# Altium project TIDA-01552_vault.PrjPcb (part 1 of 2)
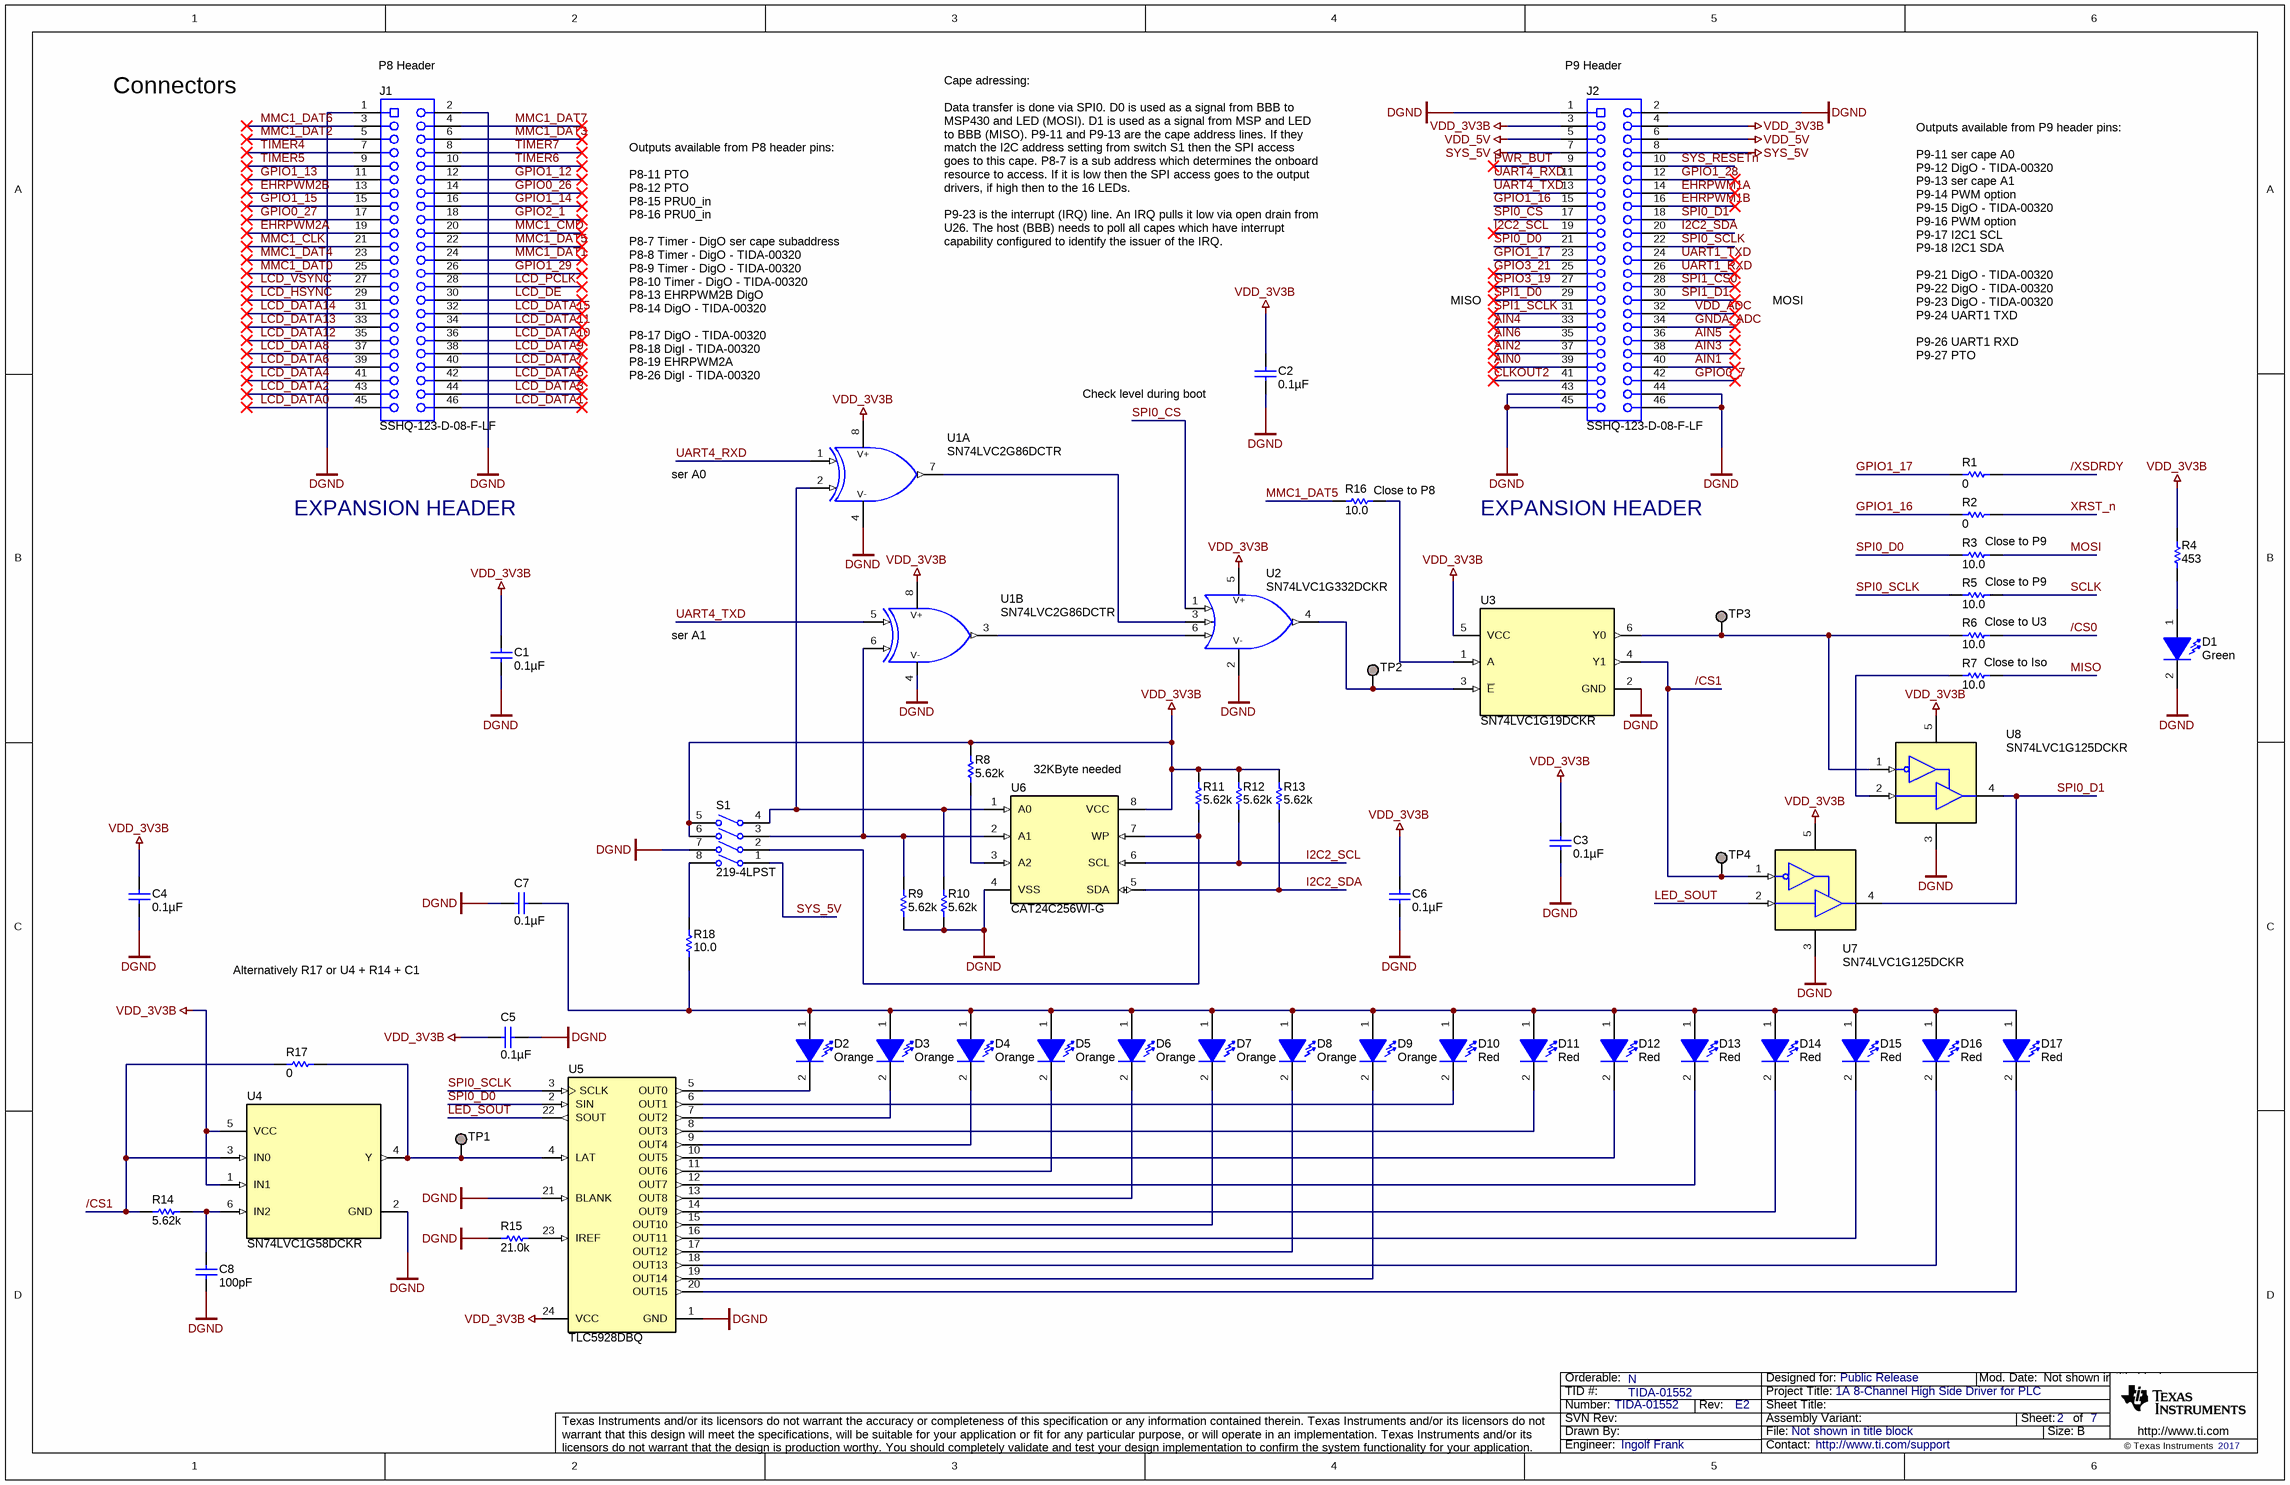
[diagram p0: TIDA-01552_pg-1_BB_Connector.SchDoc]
CopyrightYear: 2017; EVM_Orderable: N; PCB_Layout: Ingolf Frank; PCB_Rev: E2; PRJ_Customer: Public Release; PRJ_Engineer: Ingolf Frank; PRJ_Number: TIDA-01552; PRJ_Title: 1A 8-Channel High Side Driver for PLC; SCH_Rev: E2; TechSupport: http://www.ti.com/support; TID: TIDA-01552
6 sheets, 253 parts. Net scope: global (net labels, ports and power ports of the same name join across sheets).
Board file: TIDA-01552_TID.PcbDoc
Sheets:
  TIDA-01552_pg-1_BB_Connector.SchDoc
  TIDA-01552_pg-2_PSU-ISO.SchDoc
  TIDA-01552_pg-3_MCU.SchDoc
  TIDA-01552_pg-4_Driver.SchDoc
  TIDA-01552_pg-5_OP_Connector.SchDoc
  TIDA-01552_TID_Hardware.SchDoc

## Sheet TIDA-01552_pg-1_BB_Connector.SchDoc
size 431 x 279 mm; Date: Not shown in title block; ApprovedBy: Not shown in title block; CheckedBy: Not shown in title block; Author: Not shown in title block; CompanyName: Not shown in title block; Engineer: Not shown in title block; Organization: Not shown in title block; Address1: Not shown in title block; Address2: Not shown in title block; Address3: Not shown in title block; Address4: Not shown in title block; DocumentNumber: 2; Revision: Use project parameter SCH_Rev; SheetNumber: 2; SheetTotal: 7; PageSetup: Record=PageOptions¦CenterHorizontal=True¦CenterVertical=True¦PrintScale=1.00¦XCorrection=1.00¦YCorrection=1.00¦PrintKind=0¦BorderSize=5000000¦LeftOffset=0¦BottomOffset=0¦Orientation=2¦PaperLength=1000¦PaperWidth=1000¦Scale=100¦PaperSource=15¦PrintQuality=600¦MediaType=1¦DitherType=10¦PaperKind=Letter¦PrintScaleMode=1

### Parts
C1  ValueDisplayed: 0.1µF  [0603]  (hidden comment: GRM188R71C104KA01D)
C2  ValueDisplayed: 0.1µF  [0603]  (hidden comment: GRM188R71C104KA01D)
C3  ValueDisplayed: 0.1µF  [0603]  (hidden comment: GRM188R71C104KA01D)
C4  ValueDisplayed: 0.1µF  [0603]  (hidden comment: GRM188R71C104KA01D)
C5  ValueDisplayed: 0.1µF  [0603]  (hidden comment: GRM188R71C104KA01D)
C6  ValueDisplayed: 0.1µF  [0603]  (hidden comment: GRM188R71C104KA01D)
C7  ValueDisplayed: 0.1µF  [0603]  (hidden comment: GRM188R71C104KA01D)
C8  ValueDisplayed: 100pF  [0603]  (hidden comment: GRM1885C1H101JA01D)
D1  value Green  [LED_LTST-C190_G]  (hidden comment: LTST-C190KGKT)
D2  value Orange  [LED_LTST-C190]  (hidden comment: LTST-C190KFKT)
D3  value Orange  [LED_LTST-C190]  (hidden comment: LTST-C190KFKT)
D4  value Orange  [LED_LTST-C190]  (hidden comment: LTST-C190KFKT)
D5  value Orange  [LED_LTST-C190]  (hidden comment: LTST-C190KFKT)
D6  value Orange  [LED_LTST-C190]  (hidden comment: LTST-C190KFKT)
D7  value Orange  [LED_LTST-C190]  (hidden comment: LTST-C190KFKT)
D8  value Orange  [LED_LTST-C190]  (hidden comment: LTST-C190KFKT)
D9  value Orange  [LED_LTST-C190]  (hidden comment: LTST-C190KFKT)
D10  value Red  [LED_LTST-C190_Red]  (hidden comment: LTST-C190CKT)
D11  value Red  [LED_LTST-C190_Red]  (hidden comment: LTST-C190CKT)
D12  value Red  [LED_LTST-C190_Red]  (hidden comment: LTST-C190CKT)
D13  value Red  [LED_LTST-C190_Red]  (hidden comment: LTST-C190CKT)
D14  value Red  [LED_LTST-C190_Red]  (hidden comment: LTST-C190CKT)
D15  value Red  [LED_LTST-C190_Red]  (hidden comment: LTST-C190CKT)
D16  value Red  [LED_LTST-C190_Red]  (hidden comment: LTST-C190CKT)
D17  value Red  [LED_LTST-C190_Red]  (hidden comment: LTST-C190CKT)
J1  SSHQ-123-D-08-F-LF  [Major_BBB_SSHQ-123-D-08]
J2  SSHQ-123-D-08-F-LF  [Major_BBB_SSHQ-123-D-08]
R1  ValueDisplayed: 0  [0603]  (hidden comment: CRCW06030000Z0EA)
R2  ValueDisplayed: 0  [0603]  (hidden comment: CRCW06030000Z0EA)
R3  ValueDisplayed: 10.0  [0603]  (hidden comment: CRCW060310R0FKEA)
R4  ValueDisplayed: 453  [0603]  (hidden comment: CRCW0603453RFKEA)
R5  ValueDisplayed: 10.0  [0603]  (hidden comment: CRCW060310R0FKEA)
R6  ValueDisplayed: 10.0  [0603]  (hidden comment: CRCW060310R0FKEA)
R7  ValueDisplayed: 10.0  [0603]  (hidden comment: CRCW060310R0FKEA)
R8  ValueDisplayed: 5.62k  [0603]  (hidden comment: CRCW06035K62FKEA)
R9  ValueDisplayed: 5.62k  [0603]  (hidden comment: CRCW06035K62FKEA)
R10  ValueDisplayed: 5.62k  [0603]  (hidden comment: CRCW06035K62FKEA)
R11  ValueDisplayed: 5.62k  [0603]  (hidden comment: CRCW06035K62FKEA)
R12  ValueDisplayed: 5.62k  [0603]  (hidden comment: CRCW06035K62FKEA)
R13  ValueDisplayed: 5.62k  [0603]  (hidden comment: CRCW06035K62FKEA)
R14  ValueDisplayed: 5.62k  [0603]  (hidden comment: CRCW06035K62FKEA)
R15  ValueDisplayed: 21.0k  [0603]  (hidden comment: CRCW060321K0FKEA)
R16  ValueDisplayed: 10.0  [0603]  (hidden comment: CRCW060310R0FKEA)
R17  ValueDisplayed: 0  [0603]  (hidden comment: CRCW06030000Z0EA)
R18  ValueDisplayed: 10.0  [0603]  (hidden comment: CRCW060310R0FKEA)
S1  219-4LPST  [SW_219-4LPST]
TP1  Pogo Pad  [PogoPad]  (value not drawn)  (no BOM)
TP2  Pogo Pad  [PogoPad]  (value not drawn)  (no BOM)
TP3  Pogo Pad  [PogoPad]  (value not drawn)  (no BOM)
TP4  Pogo Pad  [PogoPad]  (value not drawn)  (no BOM)
U1  SN74LVC2G86DCTR  [DCT0008A_N]  (parts A,B of 2)
U2  SN74LVC1G332DCKR  [DCK0006A_N]
U3  SN74LVC1G19DCKR  [DCK0006A_N]
U4  SN74LVC1G58DCKR  [DCK0006A_N]
U5  TLC5928DBQ  [DBQ0024A_N]
U6  CAT24C256WI-G  [SOIC-8]
U7  SN74LVC1G125DCKR  [DCK0005A_N]
U8  SN74LVC1G125DCKR  [DCK0005A_N]

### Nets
DGND: C1.2 C2.2 C3.2 C4.2 C5.2 C6.2 C7.2 C8.1 D1.2(K) J1.1 J1.2 J2.1 J2.2 J2.43 J2.44 J2.45 J2.46 R9.1 R10.1 R15.2 S1.7(B2) U1.4(GND) U2.2(GND) U3.2(GND) U4.2(GND) U5.1(GND) U5.21(BLANK) U6.4(VSS) U7.3(GND) U8.3(GND)
SYS_5V: J2.7 J2.8 S1.1(A1)
VDD_3V3B: C1.1 C2.1 C3.1 C4.1 C5.1 C6.1 J2.3 J2.4 R4.2 R8.2 R11.2 R12.2 R13.2 S1.5(B4) S1.6(B3) U1.8(VCC) U2.5(VCC) U3.5(VCC) U4.1(IN1) U4.5(VCC) U5.24(VCC) U6.8(VCC) U7.5(VCC) U8.5(VCC)
VDD_5V: J2.5 J2.6
/CS0: R6.2
/CS1: R14.2 R17.1 TP4.1 U3.4(Y1) U4.3(IN0) U7.1(~{OE})
/XSDRDY: R1.2
AIN0: J2.39
AIN1: J2.40
AIN2: J2.37
AIN3: J2.38
AIN4: J2.33
AIN5: J2.36
AIN6: J2.35
CLKOUT2: J2.41
EHRPWM1A: J2.14
EHRPWM1B: J2.16
EHRPWM2A: J1.19
EHRPWM2B: J1.13
GNDA_ADC: J2.34
GPIO0_7: J2.42
GPIO0_26: J1.14
GPIO0_27: J1.17
GPIO1_12: J1.12
GPIO1_13: J1.11
GPIO1_14: J1.16
GPIO1_15: J1.15
GPIO1_16: J2.15 R2.1
GPIO1_17: J2.23 R1.1
GPIO1_28: J2.12
GPIO1_29: J1.26
GPIO2_1: J1.18
GPIO3_19: J2.27
GPIO3_21: J2.25
I2C2_SCL: J2.19 R12.1 U6.6(SCL)
I2C2_SDA: J2.20 R13.1 U6.5(SDA)
LCD_DATA0: J1.45
LCD_DATA1: J1.46
LCD_DATA2: J1.43
LCD_DATA3: J1.44
LCD_DATA4: J1.41
LCD_DATA5: J1.42
LCD_DATA6: J1.39
LCD_DATA7: J1.40
LCD_DATA8: J1.37
LCD_DATA9: J1.38
LCD_DATA10: J1.36
LCD_DATA11: J1.34
LCD_DATA12: J1.35
LCD_DATA13: J1.33
LCD_DATA14: J1.31
LCD_DATA15: J1.32
LCD_DE: J1.30
LCD_HSYNC: J1.29
LCD_PCLK: J1.28
LCD_VSYNC: J1.27
LED_SOUT: U5.22(SOUT) U7.2(A)
MISO: R7.2
MMC1_CLK: J1.21
MMC1_CMD: J1.20
MMC1_DAT0: J1.25
MMC1_DAT1: J1.24
MMC1_DAT2: J1.5
MMC1_DAT3: J1.6
MMC1_DAT4: J1.23
MMC1_DAT5: J1.22 R16.1
MMC1_DAT6: J1.3
MMC1_DAT7: J1.4
MOSI: R3.2
PWR_BUT: J2.9
SCLK: R5.2
SPI0_CS: J2.17 U2.1(A)
SPI0_D0: J2.21 R3.1 U5.2(SIN)
SPI0_D1: J2.18 U7.4(Y) U8.4(Y)
SPI0_SCLK: J2.22 R5.1 U5.3(SCLK)
SPI1_CS0: J2.28
SPI1_D0: J2.29
SPI1_D1: J2.30
SPI1_SCLK: J2.31
SYS_RESETn: J2.10
TIMER4: J1.7
TIMER5: J1.9
TIMER6: J1.10
TIMER7: J1.8
UART1_RXD: J2.26
UART1_TXD: J2.24
UART4_RXD: J2.11 U1.1(1A)
UART4_TXD: J2.13 U1.5(2A)
VDD_ADC: J2.32
XRST_n: R2.2
NetC7_1: C7.1 D2.1(A) D3.1(A) D4.1(A) D5.1(A) D6.1(A) D7.1(A) D8.1(A) D9.1(A) D10.1(A) D11.1(A) D12.1(A) D13.1(A) D14.1(A) D15.1(A) D16.1(A) D17.1(A) R18.1
NetC8_2: C8.2 R14.1 U4.6(IN2)
NetD1_1: D1.1(A) R4.1
NetD2_2: D2.2(K) U5.5(OUT0)
NetD3_2: D3.2(K) U5.7(OUT2)
NetD4_2: D4.2(K) U5.9(OUT4)
NetD5_2: D5.2(K) U5.11(OUT6)
NetD6_2: D6.2(K) U5.13(OUT8)
NetD7_2: D7.2(K) U5.15(OUT10)
NetD8_2: D8.2(K) U5.17(OUT12)
NetD9_2: D9.2(K) U5.19(OUT14)
NetD10_2: D10.2(K) U5.6(OUT1)
NetD11_2: D11.2(K) U5.8(OUT3)
NetD12_2: D12.2(K) U5.10(OUT5)
NetD13_2: D13.2(K) U5.12(OUT7)
NetD14_2: D14.2(K) U5.14(OUT9)
NetD15_2: D15.2(K) U5.16(OUT11)
NetD16_2: D16.2(K) U5.18(OUT13)
NetD17_2: D17.2(K) U5.20(OUT15)
NetR6_1: R6.1 TP3.1 U3.6(Y0) U8.1(~{OE})
NetR7_1: R7.1 U8.2(A)
NetR8_1: R8.1 U6.3(A2)
NetR9_2: R9.2 S1.3(A3) U1.6(2B) U6.2(A1)
NetR10_2: R10.2 S1.4(A4) U1.2(1B) U6.1(A0)
NetR11_1: R11.1 S1.2(A2) U6.7(WP)
NetR15_1: R15.1 U5.23(IREF)
NetR16_2: R16.2 U3.1(A)
NetR17_2: R17.2 TP1.1 U4.4(Y) U5.4(LAT)
NetR18_2: R18.2 S1.8(B1)
NetTP2_1: TP2.1 U2.4(Y) U3.3(~{E})
NetU1_3: U1.3(2Y) U2.6(C)
NetU1_7: U1.7(1Y) U2.3(B)

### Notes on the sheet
- Connectors
- (near J1) P8 Header
- (near J2) P9 Header
- Cape adressing:
  Data transfer is done via SPI0. D0 is used as a signal from BBB to MSP430 and LED (MOSI). D1 is used as a signal from MSP and LED to BBB (MISO). P9-11 and P9-13 are the cape address lines. If they match the I2C address setting from switch S1 then the SPI access goes to this cape. P8-7 is a sub address which determines the onboard resource to access. If it is low then the SPI access goes to the output drivers, if high then to the 16 LEDs.
  P9-23 is the interrupt (IRQ) line. An IRQ pulls it low via open drain from U26. The host (BBB) needs to poll all capes which have interrupt capability configured to identify the issuer of the IRQ.
- MISO
- MOSI
- Outputs available from P9 header pins:
  P9-11 ser cape A0
  P9-12 DigO - TIDA-00320
  P9-13 ser cape A1
  P9-14 PWM option
  P9-15 DigO - TIDA-00320
  P9-16 PWM option
  P9-17 I2C1 SCL
  P9-18 I2C1 SDA
  P9-21 DigO - TIDA-00320
  P9-22 DigO - TIDA-00320
  P9-23 DigO - TIDA-00320
  P9-24 UART1 TXD
  P9-26 UART1 RXD
  P9-27 PTO
  P9-41 PTO
- Outputs available from P8 header pins:
  P8-11 PTO
  P8-12 PTO
  P8-15 PRU0_in
  P8-16 PRU0_in
  P8-7 Timer - DigO ser cape subaddress
  P8-8 Timer - DigO - TIDA-00320
  P8-9 Timer - DigO - TIDA-00320
  P8-10 Timer - DigO - TIDA-00320
  P8-13 EHRPWM2B DigO
  P8-14 DigO - TIDA-00320
  P8-17 DigO - TIDA-00320
  P8-18 DigI - TIDA-00320
  P8-19 EHRPWM2A
  P8-26 DigI - TIDA-00320
- (near C2) Check level during boot
- ser A0
- (near R16) Close to P8
- EXPANSION HEADER
- (near R3) Close to P9
- ser A1
- (near R6) Close to U3
- (near R5) Close to P9
- (near R7) Close to Iso
- (near U6) 32KByte needed
- Alternatively R17 or U4 + R14 + C1

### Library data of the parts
C1-C7 = GRM188R71C104KA01D: CAP, CERM, 0.1 µF, 16 V, +/- 10%, X7R, 0603; Manufacturer: MuRata; Polarized: N; CompType: Capacitor; Value: 0.1uF; U/M: EA; Cap_F: 0.0000001; Tolerance_%: 10; Value1: Unknown; VDC_V: 16; Value2: 16V; TaMin_C: -55; TaMax_C: 125
C8 = GRM1885C1H101JA01D: CAP, CERM, 100 pF, 50 V, +/- 5%, C0G/NP0, 0603; Manufacturer: MuRata; Polarized: N; CompType: Capacitor; Value: 100pF; U/M: EA; Cap_F: 0.0000000001; Tolerance_%: 5; Value1: Unknown; VDC_V: 50; Value2: 50V; TaMin_C: -55; TaMax_C: 125
D1 = LTST-C190KGKT: LED, Green, SMD; Manufacturer: Lite-On; Type: AlInGaP; Vf_V: 2; Value2: 2V; Io_A: 0.03; Tjmax_C: 85; Value1: W; U/M: EA
D2-D9 = LTST-C190KFKT: LED, Orange, SMD; Manufacturer: Lite-On; Type: AlInGaP; Vf_V: 2; Value2: 2V; Io_A: 0.02; Power_TotalModule: 0.075; Value1: 0.075W; U/M: EA
D10-D17 = LTST-C190CKT: LED, Red, SMD; Manufacturer: Lite-On; Vf_V: 2; Value2: 2V; Io_A: 0.02; Tjmax_C: 85; Power_TotalModule: 0.0625; Value1: 0.0625W; U/M: EA
J1 J2 = SSHQ-123-D-08-F-LF: Female Connector, 2.54mm, 23x2, TH; Manufacturer: Major League Electronics; SymbolCreator: Altium; CompType: Receptacle; U/M: EA
R1 R2 R17 = CRCW06030000Z0EA: RES, 0, 5%, 0.1 W, 0603; Manufacturer: Vishay-Dale; CompType: Resistor; Value: 0; Value_Code: 0000; Tolerance_%: 5; Power_W: 0.1; Value2: 0.1W; VDC_V: 75; TempCo: 200 ppm/C; EIA_Code: E24; U/M: EA
R3 R5-R7 R16 R18 = CRCW060310R0FKEA: RES, 10.0, 1%, 0.1 W, 0603; Manufacturer: Vishay-Dale; CompType: Resistor; Value: 10.0; Res_ohm: 10; Value_Code: 10R0; Tolerance_%: 1; Power_W: 0.1; Value2: 0.1W; VDC_V: 75; TempCo: 100 ppm/C; EIA_Code: E96; U/M: EA
R4 = CRCW0603453RFKEA: RES, 453, 1%, 0.1 W, 0603; Manufacturer: Vishay-Dale; CompType: Resistor; Value: 453; Value_Code: 453R; Tolerance_%: 1; Power_W: 0.1; Value2: 0.1W; VDC_V: 75; TempCo: 100 ppm/C; EIA_Code: E96; U/M: EA
R8-R14 = CRCW06035K62FKEA: RES, 5.62 k, 1%, 0.1 W, 0603; Manufacturer: Vishay-Dale; CompType: Resistor; Value: 5.62k; Res_ohm: 5620; Value_Code: 5k62; Tolerance_%: 1; Power_W: 0.1; Value2: 0.1W; VDC_V: 75; TempCo: 100 ppm/C; EIA_Code: E96; U/M: EA
R15 = CRCW060321K0FKEA: RES, 21.0 k, 1%, 0.1 W, 0603; Manufacturer: Vishay-Dale; CompType: Resistor; Value: 21.0k; Res_ohm: 21000; Value_Code: 21k0; Tolerance_%: 1; Power_W: 0.1; Value2: 0.1W; VDC_V: 75; TempCo: 100 ppm/C; EIA_Code: E96; U/M: EA
S1 = 219-4LPST: Switch, SPST 4 Pos, Top Actuated, SMT; Manufacturer: CTS Electrocomponents; SymbolCreator: a0412235; VDC_V: 50; SwitchFunction: Off-On; PositionCount: 4; CurrentRating_mA: 100
TP1-TP4 = PogoPad: Pad for Pogo Pin Connector; SymbolCreator: codlsc
U1 = SN74LVC2G86DCTR: Dual 2-Input Exclusive-OR Gate, DCT0008A; Manufacturer: Texas Instruments; SymbolCreator: a0411947; CompType: IC; U/M: EA
U2 = SN74LVC1G332DCKR: Single 3-Input Positive-OR Gate, DCK0006A; Manufacturer: Texas Instruments; SymbolCreator: Altium; CompType: IC; U/M: EA
U3 = SN74LVC1G19DCKR: 1-OF-2 DECODER/DEMULTIPLEXER, DCK0006A; Manufacturer: Texas Instruments; SymbolCreator: Altium; CompType: IC; U/M: EA
U4 = SN74LVC1G58DCKR: Configurable Multiple-Function Gate, DCK0006A; Manufacturer: Texas Instruments; SymbolCreator: Altium; CompType: IC; U/M: EA
U5 = TLC5928DBQ: 16-Channel Constant Current LED Driver with LED Open Detection, 3 to 5.5 V, -40 to 85 degC, 24-pin SOP (DBQ24), Green (RoHS & no Sb/Br); Manufacturer: Texas Instruments; Alternate Manufacturer: None; Alternate PartNumber: Equivalent; Rating: Catalog; Vin(Max)(V): 5.5; Vin(Min)(V): 3
U6 = CAT24C256WI-G: 256 kb I2C CMOS Serial EEPROM, SOIC-8; Manufacturer: ON Semiconductor; SymbolCreator: a0411947
U7 U8 = SN74LVC1G125DCKR: Single Bus Buffer Gate With 3-State Output, DCK0005A; Alternate PartNumber: SN74LVC1G125DCKT; Manufacturer: Texas Instruments; SymbolCreator: Altium; CompType: IC; U/M: EA

## Sheet TIDA-01552_pg-2_PSU-ISO.SchDoc
size 431 x 279 mm; Date: Not shown in title block; ApprovedBy: Not shown in title block; CheckedBy: Not shown in title block; Author: Not shown in title block; CompanyName: Not shown in title block; Engineer: Not shown in title block; Organization: Not shown in title block; Address1: Not shown in title block; Address2: Not shown in title block; Address3: Not shown in title block; Address4: Not shown in title block; DocumentNumber: 3; Revision: Use project parameter SCH_Rev; SheetNumber: 3; SheetTotal: 7; PageSetup: Record=PageOptions¦CenterHorizontal=True¦CenterVertical=True¦PrintScale=1.00¦XCorrection=1.00¦YCorrection=1.00¦PrintKind=0¦BorderSize=5000000¦LeftOffset=0¦BottomOffset=0¦Orientation=2¦PaperLength=1000¦PaperWidth=1000¦Scale=100¦PaperSource=15¦PrintQuality=600¦MediaType=1¦DitherType=10¦PaperKind=Letter¦PrintScaleMode=1
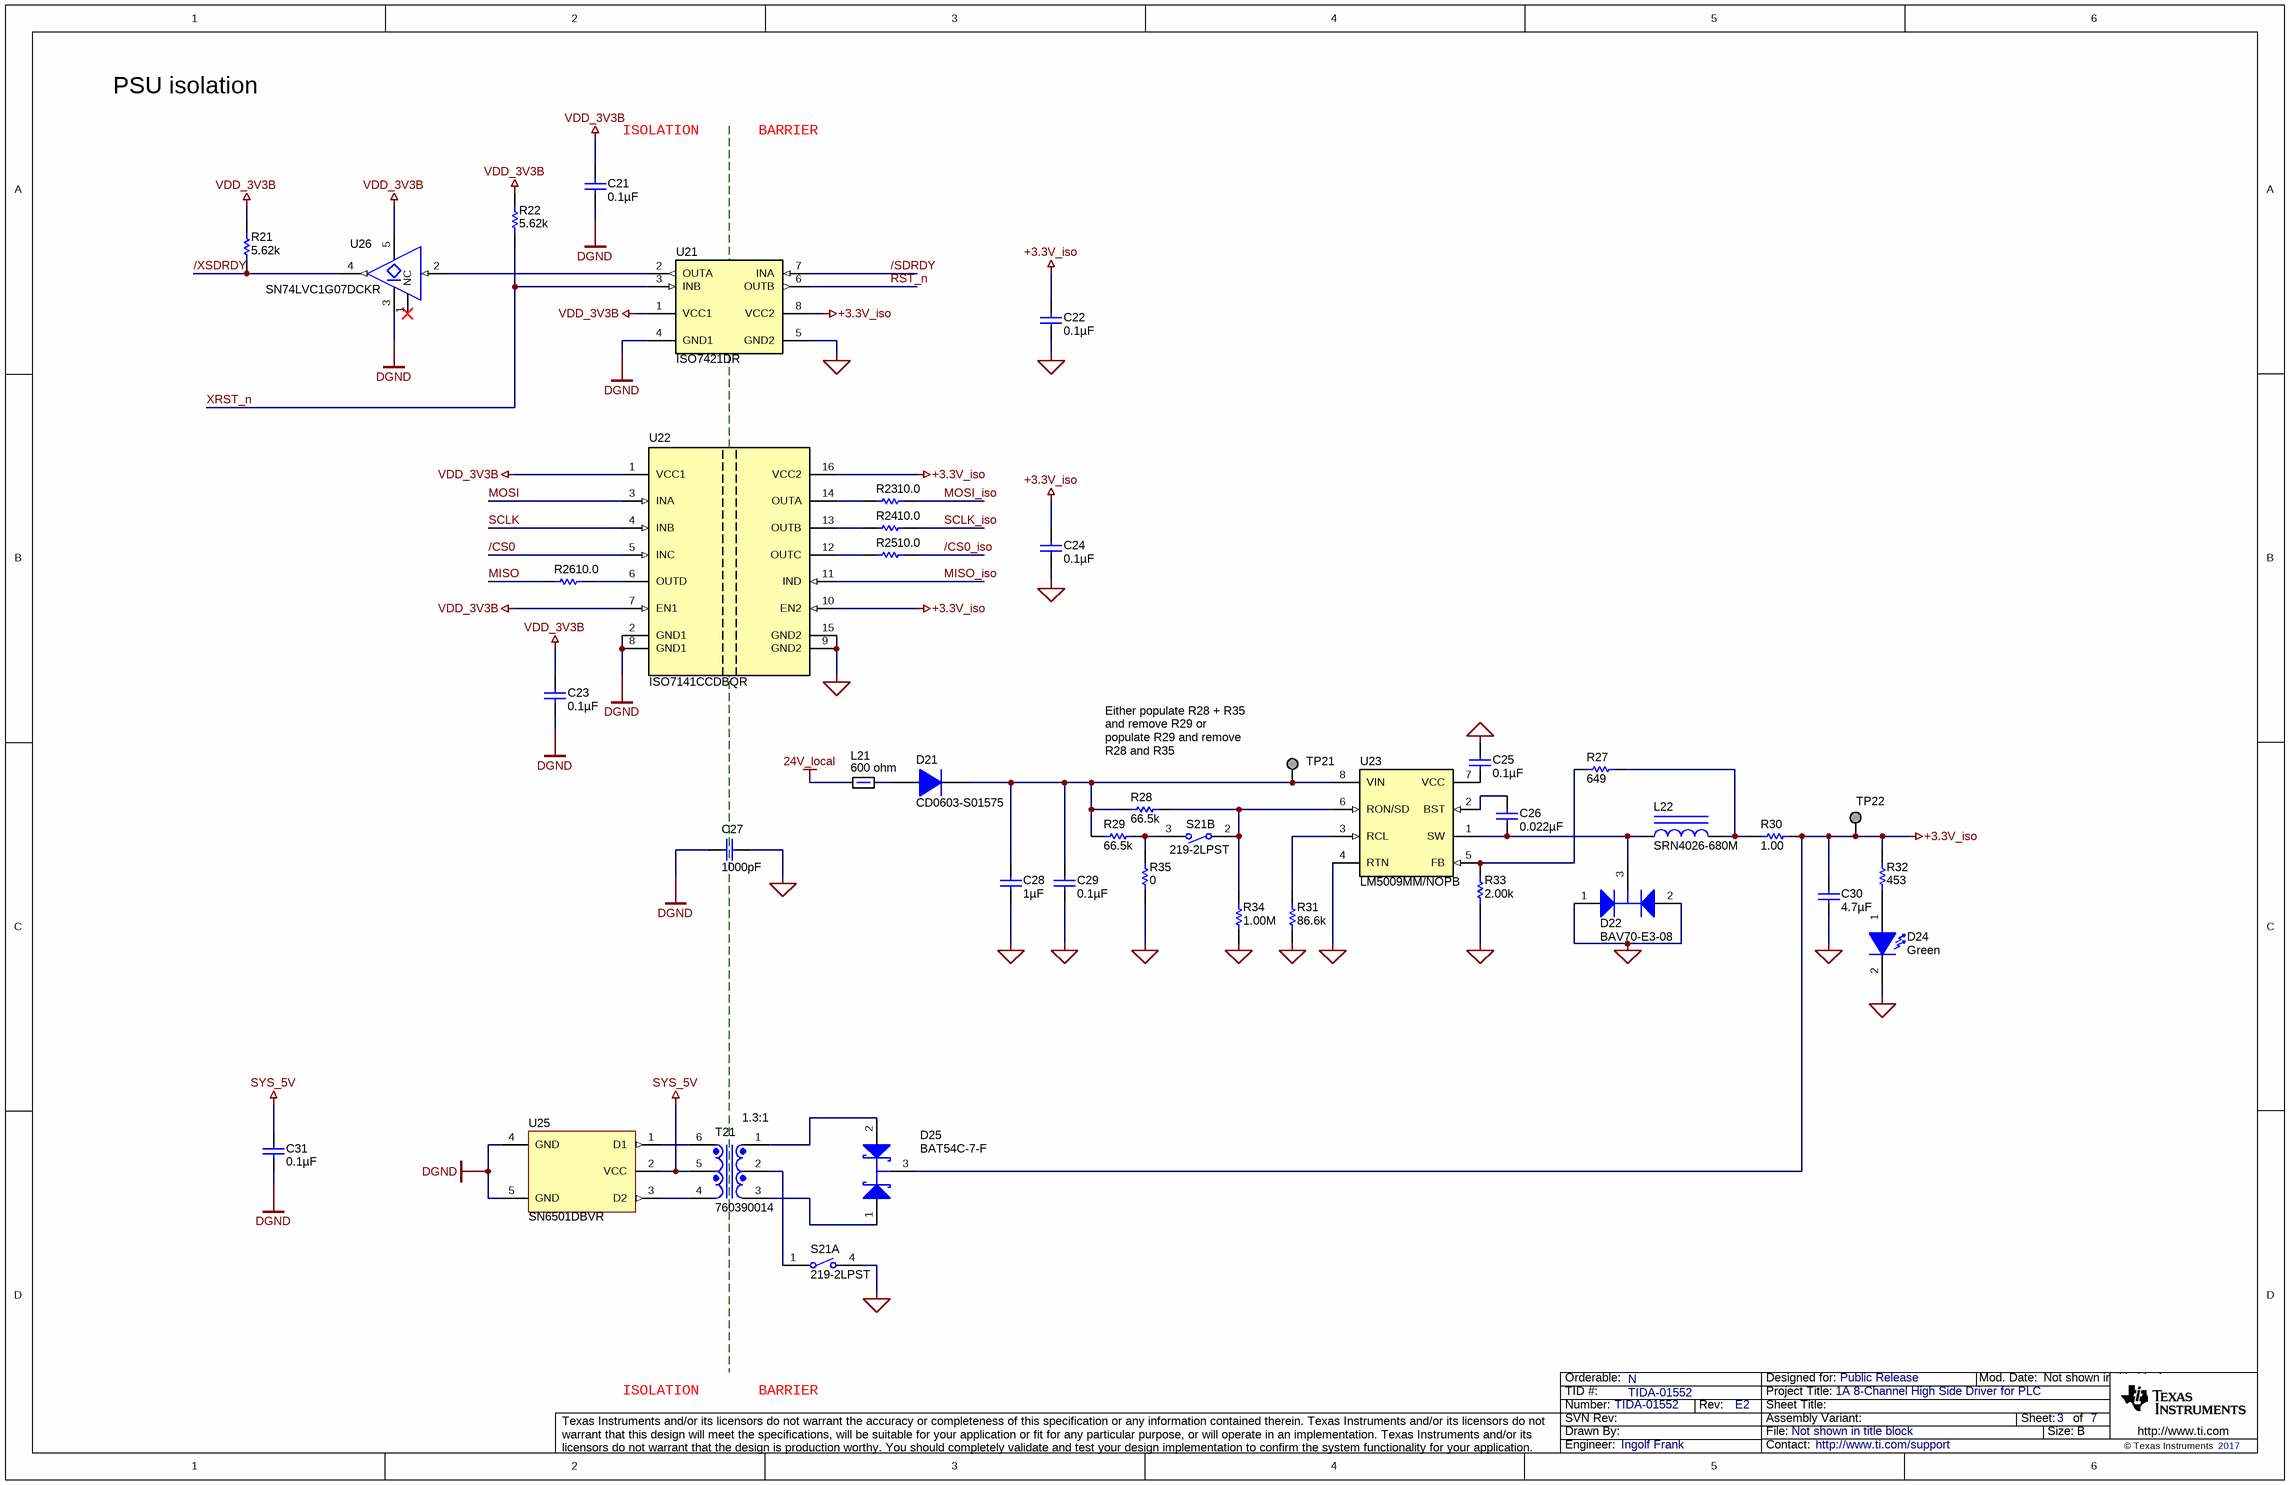
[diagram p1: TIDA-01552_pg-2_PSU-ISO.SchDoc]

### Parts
C21  ValueDisplayed: 0.1µF  [0603]  (hidden comment: GRM188R71C104KA01D)
C22  ValueDisplayed: 0.1µF  [0603]  (hidden comment: GRM188R71C104KA01D)
C23  ValueDisplayed: 0.1µF  [0603]  (hidden comment: GRM188R71C104KA01D)
C24  ValueDisplayed: 0.1µF  [0603]  (hidden comment: GRM188R71C104KA01D)
C25  ValueDisplayed: 0.1µF  [0603]  (hidden comment: GCM188R71H104KA57D)
C26  ValueDisplayed: 0.022µF  [0603]  (hidden comment: C0603C223K5RACTU)
C27  value 1000pF  [1206_190]  (hidden comment: 202R18W102KV4E)
C28  ValueDisplayed: 1µF  [0805_HV]  (hidden comment: C2012X7S2A105K125AB)
C29  ValueDisplayed: 0.1µF  [0603]  (hidden comment: GCM188R71H104KA57D)
C30  ValueDisplayed: 4.7µF  [0805_HV]  (hidden comment: GRM21BR71A475KA73L)
C31  ValueDisplayed: 0.1µF  [0603]  (hidden comment: GRM188R71C104KA01D)
D21  CD0603-S01575  [Diode_0603]
D22  BAV70-E3-08  [SOT-23]
D24  value Green  [LED_LTST-C190_G]  (hidden comment: LTST-C190KGKT)
D25  BAT54C-7-F  [SOT-23]
L21  value 600 ohm  [0603]  (hidden comment: BLM18KG601SN1D)
L22  SRN4026-680M  [SRN4026]
R21  ValueDisplayed: 5.62k  [0603]  (hidden comment: CRCW06035K62FKEA)
R22  ValueDisplayed: 5.62k  [0603]  (hidden comment: CRCW06035K62FKEA)
R23  ValueDisplayed: 10.0  [0603]  (hidden comment: CRCW060310R0FKEA)
R24  ValueDisplayed: 10.0  [0603]  (hidden comment: CRCW060310R0FKEA)
R25  ValueDisplayed: 10.0  [0603]  (hidden comment: CRCW060310R0FKEA)
R26  ValueDisplayed: 10.0  [0603]  (hidden comment: CRCW060310R0FKEA)
R27  ValueDisplayed: 649  [0603]  (hidden comment: CRCW0603649RFKEA)
R28  value 66.5k  [0603]  (hidden comment: CRCW060366K5FKEA)
R29  value 66.5k  [0603]  (hidden comment: CRCW060366K5FKEA)
R30  ValueDisplayed: 1.00  [0603]  (hidden comment: CRCW06031R00FKEA)
R31  value 86.6k  [0603]  (hidden comment: CRCW060386K6FKEA)
R32  ValueDisplayed: 453  [0603]  (hidden comment: CRCW0603453RFKEA)
R33  ValueDisplayed: 2.00k  [0603]  (hidden comment: CRCW06032K00FKEA)
R34  ValueDisplayed: 1.00M  [0603]  (hidden comment: CRCW06031M00FKEA)
R35  ValueDisplayed: 0  [0603]  (hidden comment: CRCW06030000Z0EA)
S21  219-2LPST  [SW_219-2LPST]  (parts A,B of 2)
T21  760390014  [Wurth_760390013]
TP21  Pogo Pad  [PogoPad]  (value not drawn)  (no BOM)
TP22  Pogo Pad  [PogoPad]  (value not drawn)  (no BOM)
U21  ISO7421DR  [D0008A_N]
U22  ISO7141CCDBQR  [DBQ0016A_N]
U23  LM5009MM/NOPB  [MUA08A_N]
U25  SN6501DBVR  [DBV0005A_N]
U26  SN74LVC1G07DCKR  [DCK0005A_N]

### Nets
24V_local: L21.1
+3.3V_iso: C22.1 C24.1 C30.1 D25.3(K) R30.2 R32.1 TP22.1 U21.8(VCC2) U22.10(EN2) U22.16(VCC2)
DGND: C21.2 C23.2 C27.2 C31.2 U21.4(GND1) U22.2(GND1) U22.8(GND1) U25.4(GND) U25.5(GND) U26.3(GND)
GND_SIGNAL: C22.2 C24.2 C25.1 C27.1 C28.2 C29.2 C30.2 D22.1(A) D22.2(K) D24.2(K) R31.1 R33.1 R34.1 R35.1 S21.4(1B) U21.5(GND2) U22.9(GND2) U22.15(GND2) U23.4(RTN)
SYS_5V: C31.1 T21.5 U25.2(VCC)
VDD_3V3B: C21.1 C23.1 R21.2 R22.2 U21.1(VCC1) U22.1(VCC1) U22.7(EN1) U26.5(VCC)
/CS0: U22.5(INC)
/CS0_iso: R25.1
/SDRDY: U21.7(INA)
/XSDRDY: R21.1 U26.4(Y)
MISO: R26.2
MISO_iso: U22.11(IND)
MOSI: U22.3(INA)
MOSI_iso: R23.1
RST_n: U21.6(OUTB)
SCLK: U22.4(INB)
SCLK_iso: R24.1
XRST_n: R22.1 U21.3(INB)
NetC25_2: C25.2 U23.7(VCC)
NetC26_1: C26.1 U23.2(BST)
NetC26_2: C26.2 D22.3(C) L22.1 U23.1(SW)
NetC28_1: C28.1 C29.1 D21.1(K) R28.2 R29.2 TP21.1 U23.8(VIN)
NetD21_2: D21.2(A) L21.2
NetD24_1: D24.1(A) R32.2
NetD25_1: D25.1(A1) T21.3
NetD25_2: D25.2(A2) T21.1
NetL22_2: L22.2 R27.1 R30.1
NetR23_2: R23.2 U22.14(OUTA)
NetR24_2: R24.2 U22.13(OUTB)
NetR25_2: R25.2 U22.12(OUTC)
NetR26_1: R26.1 U22.6(OUTD)
NetR27_2: R27.2 R33.2 U23.5(FB)
NetR28_1: R28.1 R34.2 S21.2(2A) U23.6(RON/SD)
NetR29_1: R29.1 R35.2 S21.3(2B)
NetR31_2: R31.2 U23.3(RCL)
NetS21_1: S21.1(1A) T21.2
NetT21_4: T21.4 U25.3(D2)
NetT21_6: T21.6 U25.1(D1)
NetU21_2: U21.2(OUTA) U26.2(A)

Not connected (* = marked no-connect by the designer): U26 1(NC)*

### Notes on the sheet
- PSU isolation
- (near C21) ISOLATION       BARRIER
- Either populate R28 + R35 and remove R29 or populate R29 and remove R28 and R35
- (near T21) 1.3:1
- ISOLATION       BARRIER

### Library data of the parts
C21-C24 C31 = GRM188R71C104KA01D: as C1 on sheet TIDA-01552_pg-1_BB_Connector
C25 C29 = GCM188R71H104KA57D: CAP, CERM, 0.1 µF, 50 V, +/- 10%, X7R, 0603; Manufacturer: MuRata; Polarized: N; CompType: Capacitor; Value: 0.1uF; U/M: EA; Cap_F: 0.0000001; Tolerance_%: 10; ESR_ohm: 0.02; Value1: 0.02 ohm; VDC_V: 50; Value2: 50V; IRMS_A: 1.84; TaMin_C: -55; TaMax_C: 125
C26 = C0603C223K5RACTU: CAP, CERM, 0.022 µF, 50 V, +/- 10%, X7R, 0603; Manufacturer: Kemet; Polarized: N; CompType: Capacitor; Value: 0.022uF; U/M: EA; Cap_F: 0.000000022; Tolerance_%: 10; Value1: Unknown; VDC_V: 50; Value2: 50V; TaMin_C: -55; TaMax_C: 125
C27 = 202R18W102KV4E: CAP, CERM, 1000 pF, 2000 V, +/- 10%, X7R, 1206_190; Manufacturer: Johanson Technology; Polarized: N; CompType: Capacitor; Cap_F: 0.000000001; Tolerance_%: 10; Value2: 2000V; Cap_Case: 1206; U/M: EA; Value1: Unknown; VDC_V: 2000; TaMin_C: -55; TaMax_C: 125
C28 = C2012X7S2A105K125AB: CAP, CERM, 1 µF, 100 V,+/- 10%, X7S, 0805; Manufacturer: TDK; Polarized: N; CompType: Capacitor; Value: 1uF; U/M: EA; Cap_F: 0.000001; Tolerance_%: 10; ESR_ohm: 0.008255; Value1: 0.008255 ohm; VDC_V: 100; Value2: 100V; IRMS_A: 2.27442; TaMin_C: -55; TaMax_C: 125; Cap_Case: 0805; SizeArea_mm2: 2.5; SizeAreaWB_mm2: 6.75; SizeX_mm: 2; SizeY_mm: 1.25; SizeZ_mm: 1.45; AEC Category: Q200; Green_Lifecycle: Active; Green_REACh: Passed
C30 = GRM21BR71A475KA73L: CAP, CERM, 4.7 µF, 10 V, +/- 10%, X7R, 0805; Manufacturer: MuRata; Polarized: N; CompType: Capacitor; Value: 4.7uF; U/M: EA; Cap_F: 0.0000047; Tolerance_%: 10; Value1: Unknown; Value2: 10V; TaMin_C: -55; TaMax_C: 125; Cap_Case: 0805
D21 = CD0603-S01575: Diode, Switching, 100 V, 0.15 A, 0603 Diode; Manufacturer: Bourns; U/M: EA; Vf_V: 1; Value: 100V; Value1: 0.15A; Value2: 1V; Io_A: 0.15; Vr_V: 100; TJmax_C: 125
D22 = BAV70-E3-08: Diode, Switching, 70 V, 0.25 A, SOT-23; Manufacturer: Vishay-Semiconductor; Value: 70V; SymbolCreator: a0412235; U/M: EA; Vf_V: 1.25; Value1: 0.25A; Value2: 1.25V; Io_A: 0.25; Vr_V: 70; TJmax_C: 150
D24 = LTST-C190KGKT: as D1 on sheet TIDA-01552_pg-1_BB_Connector
D25 = BAT54C-7-F: Diode, Schottky, 30 V, 0.2 A, SOT-23; Manufacturer: Diodes Inc.; Value: 30V; U/M: EA; Vf_V: 0.65; Value1: 0.2A; Value2: 0.65V; Io_A: 0.2; Vr_V: 30; TJmax_C: 125
L21 = BLM18KG601SN1D: Ferrite Bead, 600 ohm @ 100 MHz, 1.3 A, 0603; Manufacturer: MuRata; Imax_A: 1.3; DCR_ohm: 0.15; Value1: 0.15 ohm; Value2: 1.3A; ZTyp@100MHz_Ohm: 600
L22 = SRN4026-680M: Inductor, Wirewound, Ferrite, 68 µH, 0.35 A, 0.852 ohm, SMD; Manufacturer: Bourns; Value: 68uH; Ind_H: 68.0E-6; ValueDisplayed: 68µH; Imax_A: 0.35; Irms: 0.35A @ 40C rise; Isat: 0.35A @ 30% inductance drop; DCR_ohm: 0.852; Value2: 0.35A
R21 R22 = CRCW06035K62FKEA: as R8 on sheet TIDA-01552_pg-1_BB_Connector
R23-R26 = CRCW060310R0FKEA: as R3 on sheet TIDA-01552_pg-1_BB_Connector
R27 = CRCW0603649RFKEA: RES, 649, 1%, 0.1 W, 0603; Manufacturer: Vishay-Dale; CompType: Resistor; Value: 649; Value_Code: 649R; Tolerance_%: 1; Power_W: 0.1; Value2: 0.1W; VDC_V: 75; TempCo: 100 ppm/C; EIA_Code: E96; U/M: EA
R28 R29 = CRCW060366K5FKEA: RES, 66.5 k, 1%, 0.1 W, 0603; Manufacturer: Vishay-Dale; CompType: Resistor; Res_ohm: 66500; Value_Code: 66k5; Tolerance_%: 1; Power_W: 0.1; Value2: 0.1W; VDC_V: 75; TempCo: 100 ppm/C; EIA_Code: E96; U/M: EA
R30 = CRCW06031R00FKEA: RES, 1.00, 1%, 0.1 W, 0603; Manufacturer: Vishay-Dale; CompType: Resistor; Value: 1.00; Res_ohm: 1; Value_Code: 1R00; Power_W: 0.1; Value2: 0.1W; VDC_V: 75; TempCo: 100 ppm/C; EIA_Code: E96; U/M: EA
R31 = CRCW060386K6FKEA: RES, 86.6 k, 1%, 0.1 W, 0603; Manufacturer: Vishay-Dale; CompType: Resistor; Res_ohm: 86600; Value_Code: 86k6; Tolerance_%: 1; Power_W: 0.1; Value2: 0.1W; VDC_V: 75; TempCo: 100 ppm/C; EIA_Code: E96; U/M: EA
R32 = CRCW0603453RFKEA: as R4 on sheet TIDA-01552_pg-1_BB_Connector
R33 = CRCW06032K00FKEA: RES, 2.00 k, 1%, 0.1 W, 0603; Manufacturer: Vishay-Dale; CompType: Resistor; Value: 2.00k; Res_ohm: 2000; Value_Code: 2k00; Tolerance_%: 1; Power_W: 0.1; Value2: 0.1W; VDC_V: 75; TempCo: 100 ppm/C; EIA_Code: E96; U/M: EA
R34 = CRCW06031M00FKEA: RES, 1.00 M, 1%, 0.1 W, 0603; Manufacturer: Vishay-Dale; CompType: Resistor; Value: 1.00Meg; Res_ohm: 1000000; Value_Code: 1M00; Tolerance_%: 1; Power_W: 0.1; Value2: 0.1W; VDC_V: 75; TempCo: 100 ppm/C; EIA_Code: E96; U/M: EA
R35 = CRCW06030000Z0EA: as R1 on sheet TIDA-01552_pg-1_BB_Connector
S21 = 219-2LPST: Switch, Slide, SPST 2 poles, SMT; Manufacturer: CTS Electrocomponents; SymbolCreator: a0413446/a0412235; VDC_V: 20; SwitchFunction: Off-On; PositionCount: 2; CurrentRating_mA: 100
T21 = 760390014: Transformer, 475uH, SMT; Manufacturer: Wurth Elektronik; SymbolCreator: a0799628; DCR_Ohm: 0.31; U/M: EA
TP21 TP22 = PogoPad: as TP1 on sheet TIDA-01552_pg-1_BB_Connector
U21 = ISO7421DR: 1 Mbps Dual Channels, 1 / 1, Digital Isolator, 3.3 V / 5 V, -40 to +105 degC, 8-pin SOIC (D), Green (RoHS & no Sb/Br); Manufacturer: Texas Instruments; Alternate PartNumber: Equivalent; Datarate(Mbps): 1; Input Noise Filter: None; Insulation Rating(VRMS): 2500; Prop Delay(Max)(ns): 12; Rating: Catalog; Supply Voltage(s)(V): 3.3, 5; TTL/CMOS Input Threshold: TTL
U22 = ISO7141CCDBQR: 4242-VPK Small-Footprint and Low-Power Quad Channels Digital Isolators, DBQ0016A; Manufacturer: Texas Instruments; SymbolCreator: a0799628; CompType: IC; U/M: EA
U23 = LM5009MM/NOPB: 150 mA, 100V Step-Down Switching Regulator, 8-pin MSOP, Pb-Free; Manufacturer: Texas Instruments; PackageTopMarking: ZXTT*SLLB; PowerWise: Y; CompType: Switcher
U25 = SN6501DBVR: Low-Noise 350 mA, 410 kHz Transformer Driver, DBV0005A (SOT-23-5); Alternate PartNumber: SN6501DBVT; Manufacturer: Texas Instruments; SymbolCreator: a0411947; CompType: IC; U/M: EA; SizeArea_mm2: 8.12; SizeAreaWB_mm2: 14.82; SizeX_mm: 2.8; SizeY_mm: 2.9; SizeZ_mm: 1.45; Green_Lifecycle: Not Set; Green_REACh: Passed
U26 = SN74LVC1G07DCKR: SINGLE BUFFER/DRIVER WITH OPEN-DRAIN OUTPUT, DCK0005A (SOT-SC70-5); Alternate Manufacturer: Texas Instruments; Alternate PartNumber: SN74LVC1G07DCKT; SymbolCreator: a0411947; CompType: IC; U/M: EA; SizeArea_mm2: 4.2; SizeAreaWB_mm2: 9.3; SizeX_mm: 2.1; SizeY_mm: 2; SizeZ_mm: 1.1; Green_Lifecycle: Active; Green_REACh: Passed

## Sheet TIDA-01552_pg-3_MCU.SchDoc
size 431 x 279 mm; Date: Not shown in title block; ApprovedBy: Not shown in title block; CheckedBy: Not shown in title block; Author: Not shown in title block; CompanyName: Not shown in title block; Engineer: Not shown in title block; Organization: Not shown in title block; Address1: Not shown in title block; Address2: Not shown in title block; Address3: Not shown in title block; Address4: Not shown in title block; DocumentNumber: 4; Revision: Use project parameter SCH_Rev; SheetNumber: 4; SheetTotal: 7; PageSetup: Record=PageOptions¦CenterHorizontal=True¦CenterVertical=True¦PrintScale=1.00¦XCorrection=1.00¦YCorrection=1.00¦PrintKind=0¦BorderSize=5000000¦LeftOffset=0¦BottomOffset=0¦Orientation=2¦PaperLength=1000¦PaperWidth=1000¦Scale=100¦PaperSource=15¦PrintQuality=600¦MediaType=1¦DitherType=10¦PaperKind=Letter¦PrintScaleMode=1
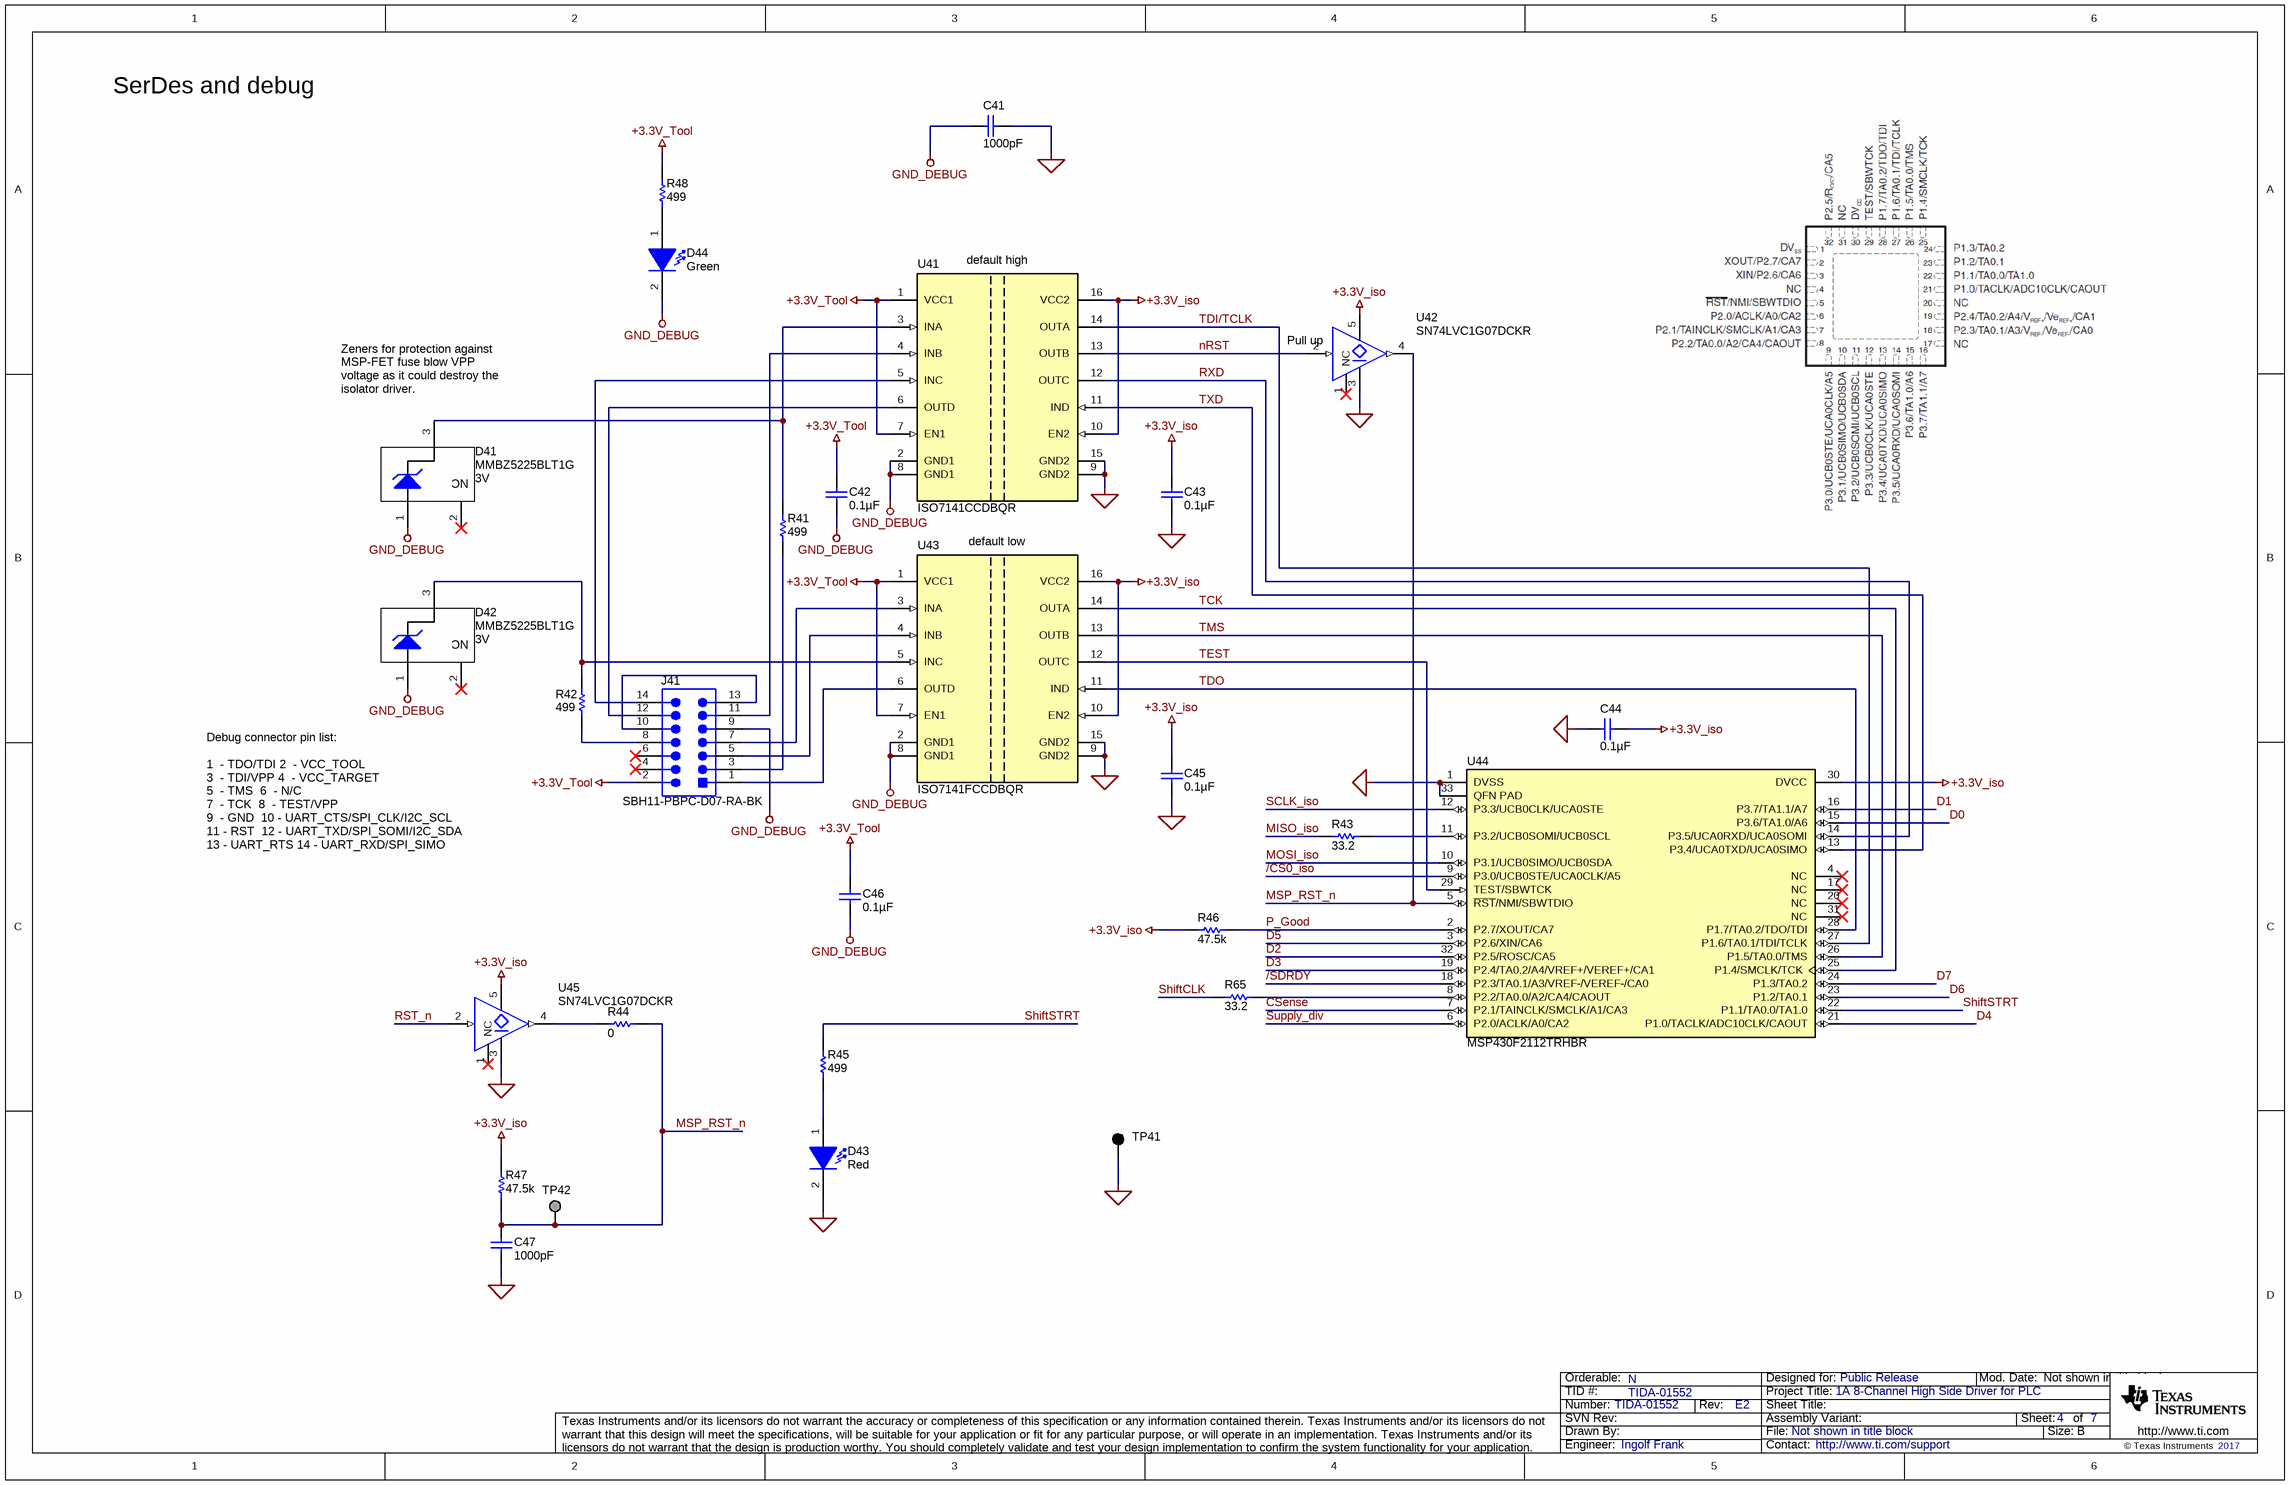
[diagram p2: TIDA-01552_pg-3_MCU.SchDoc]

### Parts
C41  value 1000pF  [1206_190]  (hidden comment: 202R18W102KV4E)
C42  ValueDisplayed: 0.1µF  [0603]  (hidden comment: GRM188R71C104KA01D)
C43  ValueDisplayed: 0.1µF  [0603]  (hidden comment: GRM188R71C104KA01D)
C44  ValueDisplayed: 0.1µF  [0603]  (hidden comment: GRM188R71C104KA01D)
C45  ValueDisplayed: 0.1µF  [0603]  (hidden comment: GRM188R71C104KA01D)
C46  ValueDisplayed: 0.1µF  [0603]  (hidden comment: GRM188R71C104KA01D)
C47  ValueDisplayed: 1000pF  [0603]  (hidden comment: GRM188R71E102KA01D)
D41  MMBZ5225BLT1G  value 3V  [SOT-23]
D42  MMBZ5225BLT1G  value 3V  [SOT-23]
D43  value Red  [LED_LTST-C190_Red]  (hidden comment: LTST-C190CKT)
D44  value Green  [LED_LTST-C190_G]  (hidden comment: LTST-C190KGKT)
J41  SBH11-PBPC-D07-RA-BK  [Sullins_SBH11-PBPC-D07-RA-BK]
R41  ValueDisplayed: 499  [0603]  (hidden comment: CRCW0603499RFKEA)
R42  ValueDisplayed: 499  [0603]  (hidden comment: CRCW0603499RFKEA)
R43  ValueDisplayed: 33.2  [0603]  (hidden comment: CRCW060333R2FKEA)
R44  ValueDisplayed: 0  [0603]  (hidden comment: CRCW06030000Z0EA)
R45  ValueDisplayed: 499  [0603]  (hidden comment: CRCW0603499RFKEA)
R46  ValueDisplayed: 47.5k  [0603]  (hidden comment: CRCW060347K5FKEA)
R47  ValueDisplayed: 47.5k  [0603]  (hidden comment: CRCW060347K5FKEA)
R48  ValueDisplayed: 499  [0603]  (hidden comment: CRCW0603499RFKEA)
R65  ValueDisplayed: 33.2  [0603]  (hidden comment: CRCW060333R2FKEA)
TP41  5001  [Keystone5001]  (value not drawn)
TP42  Pogo Pad  [PogoPad]  (value not drawn)  (no BOM)
U41  ISO7141CCDBQR  [DBQ0016A_N]
U42  SN74LVC1G07DCKR  [DCK0005A_N]
U43  ISO7141FCCDBQR  [DBQ0016A_N]
U44  MSP430F2112TRHBR  [RHB0032E]
U45  SN74LVC1G07DCKR  [DCK0005A_N]

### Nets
+3.3V_iso: C43.1 C44.1 C45.1 R46.1 R47.1 U41.10(EN2) U41.16(VCC2) U42.5(VCC) U43.10(EN2) U43.16(VCC2) U44.30(DVCC) U45.5(VCC)
+3.3V_Tool: C42.1 C46.1 J41.2 R48.2 U41.1(VCC1) U41.7(EN1) U43.1(VCC1) U43.7(EN1)
GND_DEBUG: C41.2 C42.2 C46.2 D41.1(A) D42.1(A) D44.2(K) J41.9 U41.2(GND1) U41.8(GND1) U43.2(GND1) U43.8(GND1)
GND_SIGNAL: C41.1 C43.2 C44.2 C45.2 C47.1 D43.2(K) TP41.1 U41.9(GND2) U41.15(GND2) U42.3(GND) U43.9(GND2) U43.15(GND2) U44.1(DVSS) U44.33(QFN_PAD) U45.3(GND)
/CS0_iso: U44.9(P3.0/UCB0STE/UCA0CLK/A5)
/SDRDY: U44.18(P2.3/TA0.1/A3/VREF-/VEREF-/CA0)
CSense: U44.7(P2.1/TAINCLK/SMCLK/A1/CA3)
D0: U44.15(P3.6/TA1.0/A6)
D1: U44.16(P3.7/TA1.1/A7)
D2: U44.32(P2.5/ROSC/CA5)
D3: U44.19(P2.4/TA0.2/A4/VREF+/VEREF+/CA1)
D4: U44.21(P1.0/TACLK/ADC10CLK/CAOUT)
D5: U44.3(P2.6/XIN/CA6)
D6: U44.23(P1.2/TA0.1)
D7: U44.24(P1.3/TA0.2)
MISO_iso: R43.1
MOSI_iso: U44.10(P3.1/UCB0SIMO/UCB0SDA)
MSP_RST_n: C47.2 R44.2 R47.2 TP42.1 U42.4(Y) U44.5(~{RST}/NMI/SBWTDIO)
nRST: U41.13(OUTB) U42.2(A)
P_Good: R46.2 U44.2(P2.7/XOUT/CA7)
RST_n: U45.2(A)
RXD: U41.12(OUTC) U44.14(P3.5/UCA0RXD/UCA0SOMI)
SCLK_iso: U44.12(P3.3/UCB0CLK/UCA0STE)
ShiftCLK: R65.1
ShiftSTRT: R45.2 U44.22(P1.1/TA0.0/TA1.0)
Supply_div: U44.6(P2.0/ACLK/A0/CA2)
TCK: U43.14(OUTA) U44.25(P1.4/SMCLK/TCK)
TDI/TCLK: U41.14(OUTA) U44.27(P1.6/TA0.1/TDI/TCLK)
TDO: U43.11(IND) U44.28(P1.7/TA0.2/TDO/TDI)
TEST: U43.12(OUTC) U44.29(TEST/SBWTCK)
TMS: U43.13(OUTB) U44.26(P1.5/TA0.0/TMS)
TXD: U41.11(IND) U44.13(P3.4/UCA0TXD/UCA0SIMO)
NetD41_3: D41.3(K) R41.2 U41.3(INA)
NetD42_3: D42.3(K) R42.2 U43.5(INC)
NetD43_1: D43.1(A) R45.1
NetD44_1: D44.1(A) R48.1
NetJ41_1: J41.1 U43.6(OUTD)
NetJ41_3: J41.3 R41.1
NetJ41_5: J41.5 U43.4(INB)
NetJ41_7: J41.7 U43.3(INA)
NetJ41_8: J41.8 R42.1
NetJ41_10: J41.10 J41.13
NetJ41_11: J41.11 U41.4(INB)
NetJ41_12: J41.12 U41.6(OUTD)
NetJ41_14: J41.14 U41.5(INC)
NetR43_2: R43.2 U44.11(P3.2/UCB0SOMI/UCB0SCL)
NetR44_1: R44.1 U45.4(Y)
NetR65_2: R65.2 U44.8(P2.2/TA0.0/A2/CA4/CAOUT)

Not connected (* = marked no-connect by the designer): D41 2(NC)*; D42 2(NC)*; J41 4* 6*; U42 1(NC)*; U44 4(NC)* 17(NC)* 20(NC)* 31(NC)*; U45 1(NC)*

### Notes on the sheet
- SerDes and debug
- (near U41) default high
- (near U42) Pull up
- (near D41) Zeners for protection against MSP-FET fuse blow VPP voltage as it could destroy the isolator driver.
- (near U43) default low
- Debug connector pin list:
  1  - TDO/TDI	2  - VCC_TOOL
  3  - TDI/VPP	4  - VCC_TARGET
  5  - TMS		6  - N/C
  7  - TCK		8  - TEST/VPP
  9  - GND		10 - UART_CTS/SPI_CLK/I2C_SCL
  11 - RST		12 - UART_TXD/SPI_SOMI/I2C_SDA
  13 - UART_RTS	14 - UART_RXD/SPI_SIMO

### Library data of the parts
C41 = 202R18W102KV4E: as C27 on sheet TIDA-01552_pg-2_PSU-ISO
C42-C46 = GRM188R71C104KA01D: as C1 on sheet TIDA-01552_pg-1_BB_Connector
C47 = GRM188R71E102KA01D: CAP, CERM, 1000 pF, 25 V, +/- 10%, X7R, 0603; Manufacturer: MuRata; Polarized: N; CompType: Capacitor; Value: 1000pF; U/M: EA; Cap_F: 0.000000001; Tolerance_%: 10; Value1: Unknown; VDC_V: 25; Value2: 25V; TaMin_C: -55; TaMax_C: 125
D41 D42 = MMBZ5225BLT1G: Diode, Zener, 3 V, 225 mW, SOT-23; Manufacturer: ON Semiconductor; U/M: EA; Power_W: 0.225; Vz_V: 3; Value1: 0.225W; RJA_CperW: 556
D43 = LTST-C190CKT: as D10 on sheet TIDA-01552_pg-1_BB_Connector
D44 = LTST-C190KGKT: as D1 on sheet TIDA-01552_pg-1_BB_Connector
J41 = SBH11-PBPC-D07-RA-BK: Header (Shrouded), 2.54 mm, 7x2, Gold, R/A, TH; Manufacturer: Sullins Connector Solutions; SymbolCreator: a0412235; U/M: EA
R41 R42 R45 R48 = CRCW0603499RFKEA: RES, 499, 1%, 0.1 W, 0603; Manufacturer: Vishay-Dale; CompType: Resistor; Value: 499; Value_Code: 499R; Tolerance_%: 1; Power_W: 0.1; Value2: 0.1W; VDC_V: 75; TempCo: 100 ppm/C; EIA_Code: E96; U/M: EA
R43 R65 = CRCW060333R2FKEA: RES, 33.2, 1%, 0.1 W, 0603; Manufacturer: Vishay-Dale; CompType: Resistor; Value: 33.2; Value_Code: 33R2; Tolerance_%: 1; Power_W: 0.1; Value2: 0.1W; VDC_V: 75; TempCo: 100 ppm/C; EIA_Code: E96; U/M: EA
R44 = CRCW06030000Z0EA: as R1 on sheet TIDA-01552_pg-1_BB_Connector
R46 R47 = CRCW060347K5FKEA: RES, 47.5 k, 1%, 0.1 W, 0603; Manufacturer: Vishay-Dale; CompType: Resistor; Value: 47.5k; Res_ohm: 47500; Value_Code: 47k5; Tolerance_%: 1; Power_W: 0.1; Value2: 0.1W; VDC_V: 75; TempCo: 100 ppm/C; EIA_Code: E96; U/M: EA
TP41 = 5001: Test Point, Miniature, Black, TH; Manufacturer: Keystone; CompType: Test Point Loop; U/M: EA
TP42 = PogoPad: as TP1 on sheet TIDA-01552_pg-1_BB_Connector
U41 = ISO7141CCDBQR: as U22 on sheet TIDA-01552_pg-2_PSU-ISO
U42 U45 = SN74LVC1G07DCKR: as U26 on sheet TIDA-01552_pg-2_PSU-ISO
U43 = ISO7141FCCDBQR: 4242-VPK Small-Footprint and Low-Power Quad Channels Digital Isolators, DBQ0016A; Manufacturer: Texas Instruments; SymbolCreator: a0799628; CompType: IC; U/M: EA
U44 = MSP430F2112TRHBR: 16 MHz Mixed Signal Microcontroller with 2 KB Flash, 256 B SRAM and 24 GPIOs, -40 to 105 degC, 32-pin QFN (RHB), Green (RoHS & no Sb/Br); Alternate Manufacturer: Texas Instruments; Alternate PartNumber: Equivalent; ADC: 10-bit SAR; ADC Channels: 8; Brown Out Reset: Yes; Flash(KB): 2; Frequency(MHz): 16; GPIO: 24; Pin/Package: 28TSSOP, 32QFN, 32WQFN; SRAM(B): 256; SubFamily: 2 Series, Extended Temp; USCI_A (UART/LIN/IrDA/SPI): 1

## Sheet TIDA-01552_pg-4_Driver.SchDoc
size 431 x 279 mm; Date: Not shown in title block; ApprovedBy: Not shown in title block; CheckedBy: Not shown in title block; Author: Not shown in title block; CompanyName: Not shown in title block; Engineer: Not shown in title block; Organization: Not shown in title block; Address1: Not shown in title block; Address2: Not shown in title block; Address3: Not shown in title block; Address4: Not shown in title block; DocumentNumber: 5; Revision: Use project parameter SCH_Rev; SheetNumber: 5; SheetTotal: 7; PageSetup: Record=PageOptions¦CenterHorizontal=True¦CenterVertical=True¦PrintScale=1.00¦XCorrection=1.00¦YCorrection=1.00¦PrintKind=0¦BorderSize=5000000¦LeftOffset=0¦BottomOffset=0¦Orientation=2¦PaperLength=1000¦PaperWidth=1000¦Scale=100¦PaperSource=15¦PrintQuality=600¦MediaType=1¦DitherType=10¦PaperKind=Letter¦PrintScaleMode=1
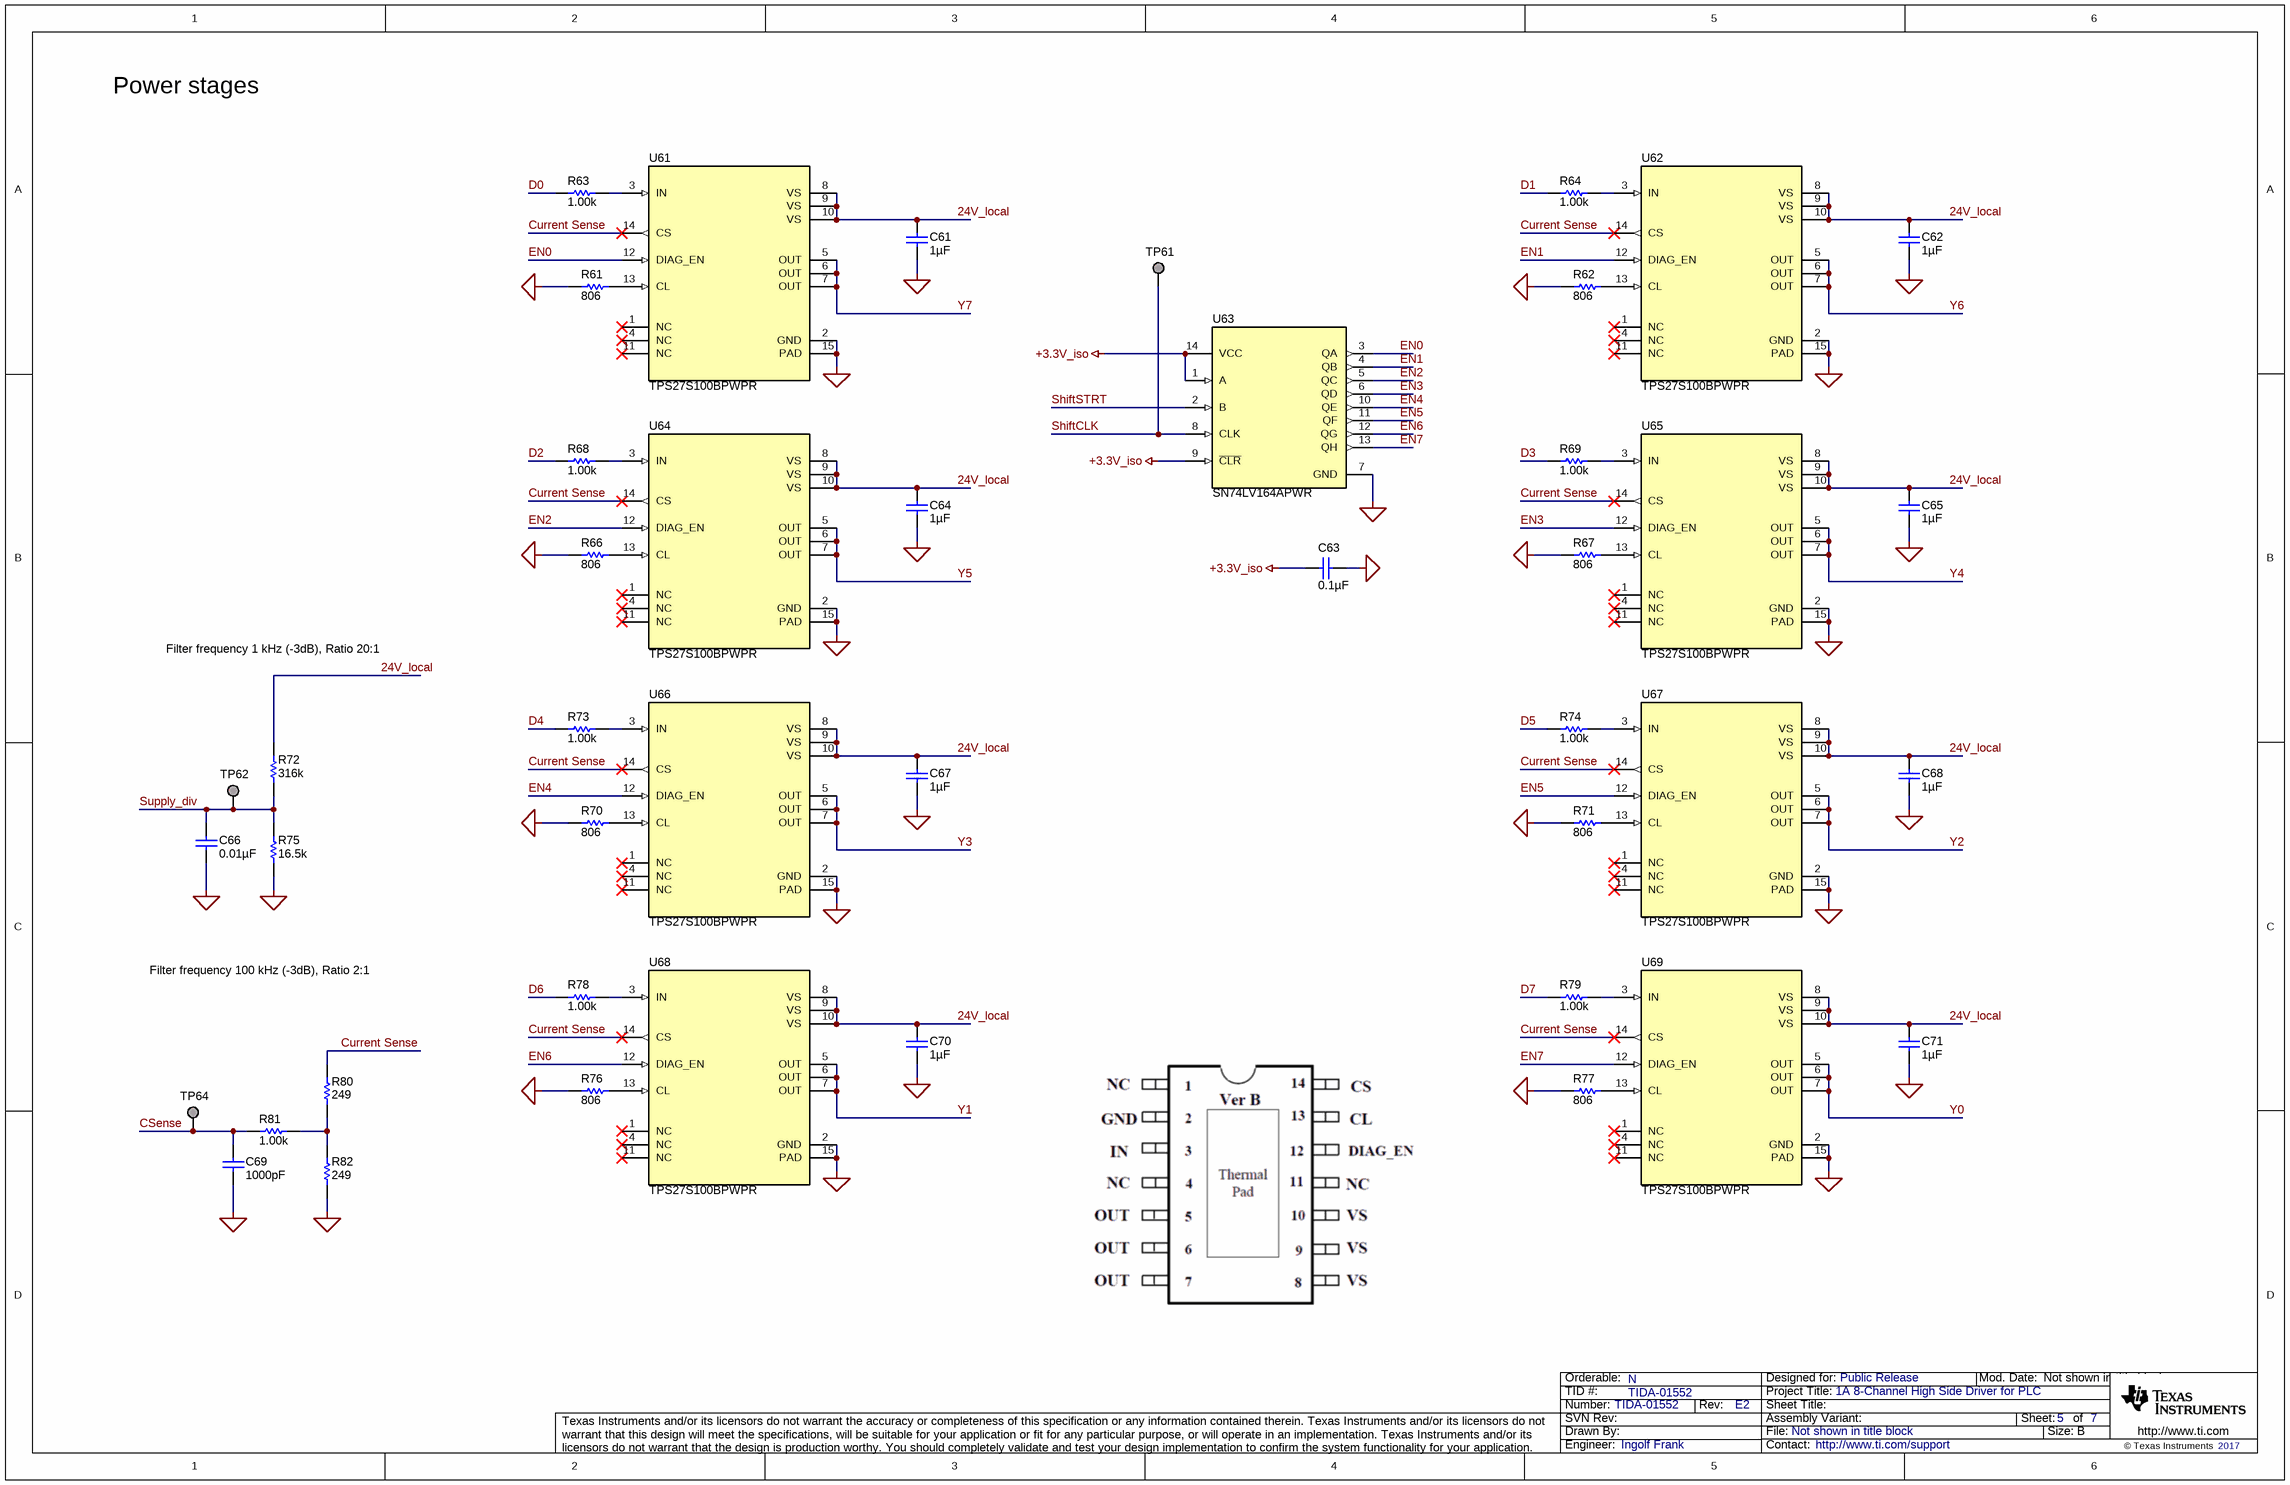
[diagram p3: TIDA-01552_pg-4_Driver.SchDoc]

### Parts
C61  ValueDisplayed: 1µF  [0805L]  (hidden comment: C2012X7S2A105K125AB)
C62  ValueDisplayed: 1µF  [0805L]  (hidden comment: C2012X7S2A105K125AB)
C63  ValueDisplayed: 0.1µF  [0603]  (hidden comment: GRM188R71C104KA01D)
C64  ValueDisplayed: 1µF  [0805L]  (hidden comment: C2012X7S2A105K125AB)
C65  ValueDisplayed: 1µF  [0805L]  (hidden comment: C2012X7S2A105K125AB)
C66  ValueDisplayed: 0.01µF  [0603]  (hidden comment: CGA3E2X7R2A103K080AA)
C67  ValueDisplayed: 1µF  [0805L]  (hidden comment: C2012X7S2A105K125AB)
C68  ValueDisplayed: 1µF  [0805L]  (hidden comment: C2012X7S2A105K125AB)
C69  ValueDisplayed: 1000pF  [0603]  (hidden comment: GRM188R71E102KA01D)
C70  ValueDisplayed: 1µF  [0805L]  (hidden comment: C2012X7S2A105K125AB)
C71  ValueDisplayed: 1µF  [0805L]  (hidden comment: C2012X7S2A105K125AB)
R61  ValueDisplayed: 806  [0603]  (hidden comment: CRCW0603806RFKEA)
R62  ValueDisplayed: 806  [0603]  (hidden comment: CRCW0603806RFKEA)
R63  ValueDisplayed: 1.00k  [0603]  (hidden comment: CRCW06031K00FKEA)
R64  ValueDisplayed: 1.00k  [0603]  (hidden comment: CRCW06031K00FKEA)
R66  ValueDisplayed: 806  [0603]  (hidden comment: CRCW0603806RFKEA)
R67  ValueDisplayed: 806  [0603]  (hidden comment: CRCW0603806RFKEA)
R68  ValueDisplayed: 1.00k  [0603]  (hidden comment: CRCW06031K00FKEA)
R69  ValueDisplayed: 1.00k  [0603]  (hidden comment: CRCW06031K00FKEA)
R70  ValueDisplayed: 806  [0603]  (hidden comment: CRCW0603806RFKEA)
R71  ValueDisplayed: 806  [0603]  (hidden comment: CRCW0603806RFKEA)
R72  ValueDisplayed: 316k  [0603]  (hidden comment: CRCW0603316KFKEA)
R73  ValueDisplayed: 1.00k  [0603]  (hidden comment: CRCW06031K00FKEA)
R74  ValueDisplayed: 1.00k  [0603]  (hidden comment: CRCW06031K00FKEA)
R75  ValueDisplayed: 16.5k  [0603]  (hidden comment: CRCW060316K5FKEA)
R76  ValueDisplayed: 806  [0603]  (hidden comment: CRCW0603806RFKEA)
R77  ValueDisplayed: 806  [0603]  (hidden comment: CRCW0603806RFKEA)
R78  ValueDisplayed: 1.00k  [0603]  (hidden comment: CRCW06031K00FKEA)
R79  ValueDisplayed: 1.00k  [0603]  (hidden comment: CRCW06031K00FKEA)
R80  ValueDisplayed: 249  [0603]  (hidden comment: CRCW0603249RFKEA)
R81  ValueDisplayed: 1.00k  [0603]  (hidden comment: CRCW06031K00FKEA)
R82  ValueDisplayed: 249  [0603]  (hidden comment: CRCW0603249RFKEA)
TP61  Pogo Pad  [PogoPad]  (value not drawn)  (no BOM)
TP62  Pogo Pad  [PogoPad]  (value not drawn)  (no BOM)
TP64  Pogo Pad  [PogoPad]  (value not drawn)  (no BOM)
U61  TPS27S100BPWPR  [PWP0014A_N]
U62  TPS27S100BPWPR  [PWP0014A_N]
U63  SN74LV164APWR  [PW0014A_N]
U64  TPS27S100BPWPR  [PWP0014A_N]
U65  TPS27S100BPWPR  [PWP0014A_N]
U66  TPS27S100BPWPR  [PWP0014A_N]
U67  TPS27S100BPWPR  [PWP0014A_N]
U68  TPS27S100BPWPR  [PWP0014A_N]
U69  TPS27S100BPWPR  [PWP0014A_N]

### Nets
24V_local: C61.1 C62.1 C64.1 C65.1 C67.1 C68.1 C70.1 C71.1 R72.2 U61.8(VS) U61.9(VS) U61.10(VS) U62.8(VS) U62.9(VS) U62.10(VS) U64.8(VS) U64.9(VS) U64.10(VS) U65.8(VS) U65.9(VS) U65.10(VS) U66.8(VS) U66.9(VS) U66.10(VS) U67.8(VS) U67.9(VS) U67.10(VS) U68.8(VS) U68.9(VS) U68.10(VS) U69.8(VS) U69.9(VS) U69.10(VS)
+3.3V_iso: C63.1 U63.1(A) U63.9(~{CLR}) U63.14(VCC)
GND_SIGNAL: C61.2 C62.2 C63.2 C64.2 C65.2 C66.2 C67.2 C68.2 C69.2 C70.2 C71.2 R61.2 R62.2 R66.2 R67.2 R70.2 R71.2 R75.1 R76.2 R77.2 R82.1 U61.2(GND) U61.15(PAD) U62.2(GND) U62.15(PAD) U63.7(GND) U64.2(GND) U64.15(PAD) U65.2(GND) U65.15(PAD) U66.2(GND) U66.15(PAD) U67.2(GND) U67.15(PAD) U68.2(GND) U68.15(PAD) U69.2(GND) U69.15(PAD)
CSense: C69.1 R81.1 TP64.1
Current Sense: R80.2 U61.14(CS) U62.14(CS) U64.14(CS) U65.14(CS) U66.14(CS) U67.14(CS) U68.14(CS) U69.14(CS)
D0: R63.1
D1: R64.1
D2: R68.1
D3: R69.1
D4: R73.1
D5: R74.1
D6: R78.1
D7: R79.1
EN0: U61.12(DIAG_EN) U63.3(QA)
EN1: U62.12(DIAG_EN) U63.4(QB)
EN2: U63.5(QC) U64.12(DIAG_EN)
EN3: U63.6(QD) U65.12(DIAG_EN)
EN4: U63.10(QE) U66.12(DIAG_EN)
EN5: U63.11(QF) U67.12(DIAG_EN)
EN6: U63.12(QG) U68.12(DIAG_EN)
EN7: U63.13(QH) U69.12(DIAG_EN)
ShiftCLK: TP61.1 U63.8(CLK)
ShiftSTRT: U63.2(B)
Supply_div: C66.1 R72.1 R75.2 TP62.1
Y0: U69.5(OUT) U69.6(OUT) U69.7(OUT)
Y1: U68.5(OUT) U68.6(OUT) U68.7(OUT)
Y2: U67.5(OUT) U67.6(OUT) U67.7(OUT)
Y3: U66.5(OUT) U66.6(OUT) U66.7(OUT)
Y4: U65.5(OUT) U65.6(OUT) U65.7(OUT)
Y5: U64.5(OUT) U64.6(OUT) U64.7(OUT)
Y6: U62.5(OUT) U62.6(OUT) U62.7(OUT)
Y7: U61.5(OUT) U61.6(OUT) U61.7(OUT)
NetR61_1: R61.1 U61.13(CL)
NetR62_1: R62.1 U62.13(CL)
NetR63_2: R63.2 U61.3(IN)
NetR64_2: R64.2 U62.3(IN)
NetR66_1: R66.1 U64.13(CL)
NetR67_1: R67.1 U65.13(CL)
NetR68_2: R68.2 U64.3(IN)
NetR69_2: R69.2 U65.3(IN)
NetR70_1: R70.1 U66.13(CL)
NetR71_1: R71.1 U67.13(CL)
NetR73_2: R73.2 U66.3(IN)
NetR74_2: R74.2 U67.3(IN)
NetR76_1: R76.1 U68.13(CL)
NetR77_1: R77.1 U69.13(CL)
NetR78_2: R78.2 U68.3(IN)
NetR79_2: R79.2 U69.3(IN)
NetR80_1: R80.1 R81.2 R82.2

Not connected (* = marked no-connect by the designer): U61 1(NC)* 4(NC)* 11(NC)*; U62 1(NC)* 4(NC)* 11(NC)*; U64 1(NC)* 4(NC)* 11(NC)*; U65 1(NC)* 4(NC)* 11(NC)*; U66 1(NC)* 4(NC)* 11(NC)*; U67 1(NC)* 4(NC)* 11(NC)*; U68 1(NC)* 4(NC)* 11(NC)*; U69 1(NC)* 4(NC)* 11(NC)*

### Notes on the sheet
- Power stages
- Filter frequency 1 kHz (-3dB), Ratio 20:1
- Filter frequency 100 kHz (-3dB), Ratio 2:1

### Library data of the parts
C61 C62 C64 C65 C67 C68 C70 C71 = C2012X7S2A105K125AB: as C28 on sheet TIDA-01552_pg-2_PSU-ISO
C63 = GRM188R71C104KA01D: as C1 on sheet TIDA-01552_pg-1_BB_Connector
C66 = CGA3E2X7R2A103K080AA: CAP, CERM, 0.01 µF, 100 V,+/- 10%, X7R, AEC-Q200 Grade 1, 0603; Manufacturer: TDK; Polarized: N; CompType: Capacitor; Value: 0.01uF; U/M: EA; Cap_F: 0.00000001; Tolerance_%: 10; ESR_ohm: 0.235428; Value1: 0.235428 ohm; VDC_V: 100; Value2: 100V; IRMS_A: 0.396995; TaMin_C: -55; TaMax_C: 125; SizeArea_mm2: 1.28; SizeAreaWB_mm2: 4.68; SizeX_mm: 1.6; SizeY_mm: 0.8; SizeZ_mm: 1; AEC Category: Q200; AEC Qualified: Y
C69 = GRM188R71E102KA01D: as C47 on sheet TIDA-01552_pg-3_MCU
R61 R62 R66 R67 R70 R71 R76 R77 = CRCW0603806RFKEA: RES, 806, 1%, 0.1 W, 0603; Manufacturer: Vishay-Dale; CompType: Resistor; Value: 806; Value_Code: 806R; Tolerance_%: 1; Power_W: 0.1; Value2: 0.1W; VDC_V: 75; TempCo: 100 ppm/C; EIA_Code: E96; U/M: EA
R63 R64 R68 R69 R73 R74 R78 R79 R81 = CRCW06031K00FKEA: RES, 1.00 k, 1%, 0.1 W, 0603; Manufacturer: Vishay-Dale; CompType: Resistor; Value: 1.00k; Res_ohm: 1000; Value_Code: 1k00; Tolerance_%: 1; Power_W: 0.1; Value2: 0.1W; VDC_V: 75; TempCo: 100 ppm/C; EIA_Code: E96; U/M: EA
R72 = CRCW0603316KFKEA: RES, 316 k, 1%, 0.1 W, 0603; Manufacturer: Vishay-Dale; CompType: Resistor; Value: 316k; Res_ohm: 316000; Tolerance_%: 1; Power_W: 0.1; Value2: 0.1W; VDC_V: 75; TempCo: 100 ppm/C; EIA_Code: E96; U/M: EA
R75 = CRCW060316K5FKEA: RES, 16.5 k, 1%, 0.1 W, 0603; Manufacturer: Vishay-Dale; CompType: Resistor; Value: 16.5k; Res_ohm: 16500; Value_Code: 16k5; Tolerance_%: 1; Power_W: 0.1; Value2: 0.1W; VDC_V: 75; TempCo: 100 ppm/C; EIA_Code: E96; U/M: EA
R80 R82 = CRCW0603249RFKEA: RES, 249, 1%, 0.1 W, 0603; Manufacturer: Vishay-Dale; CompType: Resistor; Value: 249; Value_Code: 249R; Tolerance_%: 1; Power_W: 0.1; Value2: 0.1W; VDC_V: 75; TempCo: 100 ppm/C; EIA_Code: E96; U/M: EA
TP61 TP62 TP64 = PogoPad: as TP1 on sheet TIDA-01552_pg-1_BB_Connector
U61 U62 U64-U69 = CMP-0077266-1: 40 V, 80 mOhm Single-Channel High-Side Switch, PWP0014C (TSSOP-14); Alternate PartNumber: TPS27S100BPWPT; Alternate Manufacturer: Texas Instruments; SizeAreaWB_mm2: 58.8; SizeZ_mm: 1.2; SizeX_mm: 6.4; SizeY_mm: 5.0; SizeArea_mm2: 32.0; CompType: IC; AEC Qualified: N; AEC Category: Q200
U63 = SN74LV164APWR: 8-BIT PARALLEL-OUT SERIAL SHIFT REGISTERS, PW0014A; Alternate PartNumber: SN74LV164APWT; Manufacturer: Texas Instruments; SymbolCreator: Altium; CompType: IC; U/M: EA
